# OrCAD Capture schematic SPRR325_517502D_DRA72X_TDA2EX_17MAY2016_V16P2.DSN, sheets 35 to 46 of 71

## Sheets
35 SH45 - SERDES CLOCK: size B; rev: A
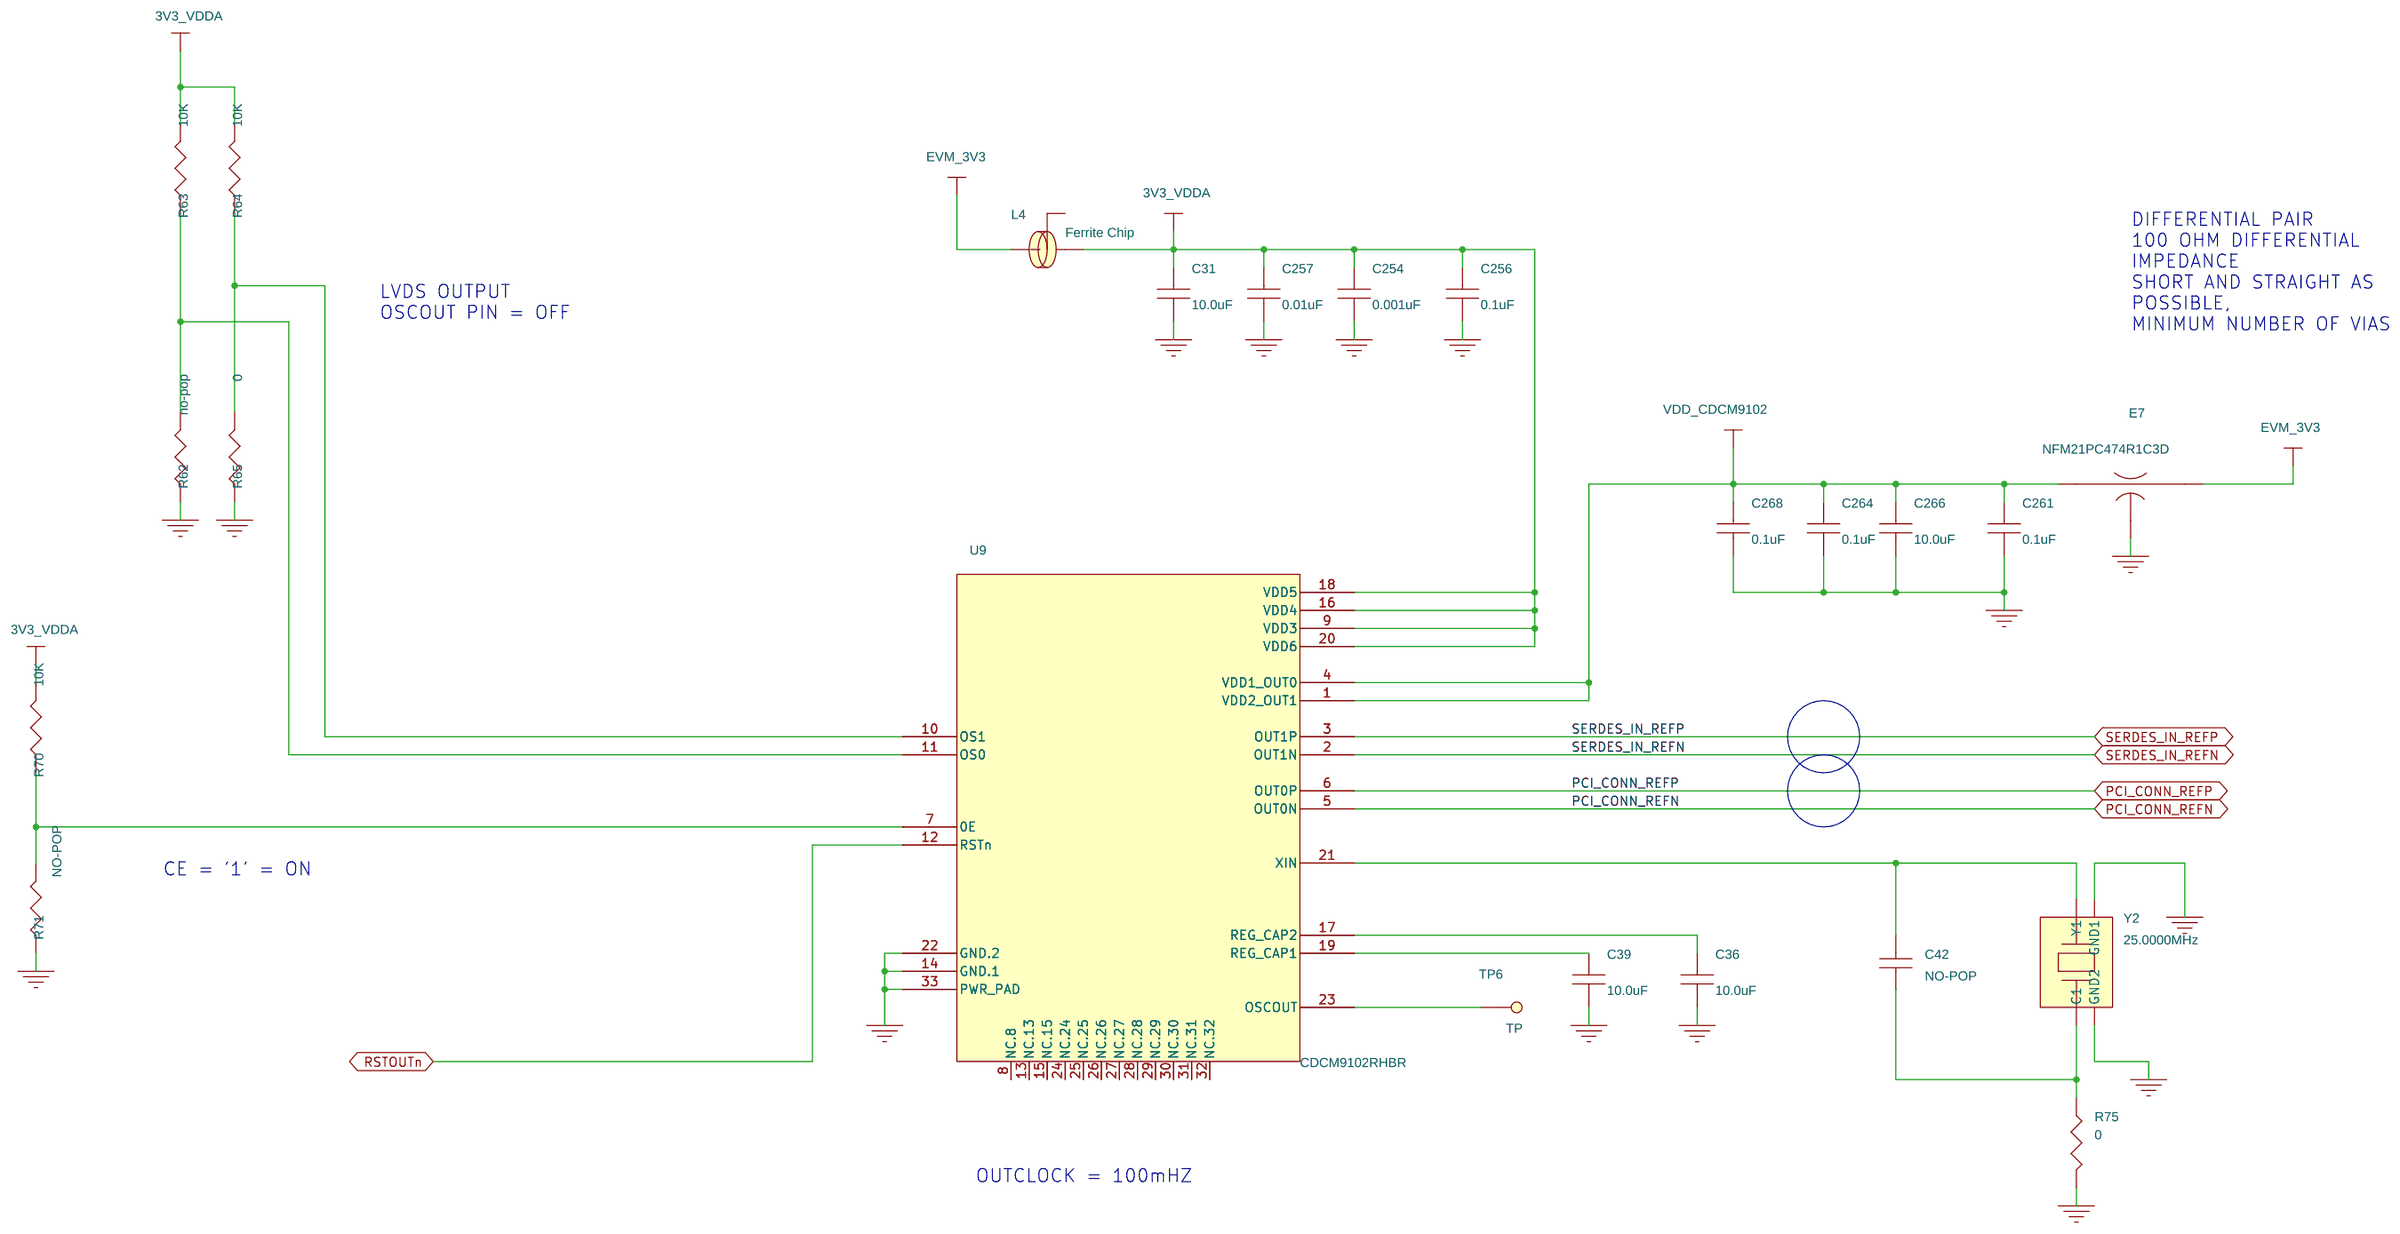
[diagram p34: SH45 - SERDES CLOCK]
36 SH46 - PCIe CONNECTORS: size B; rev: B
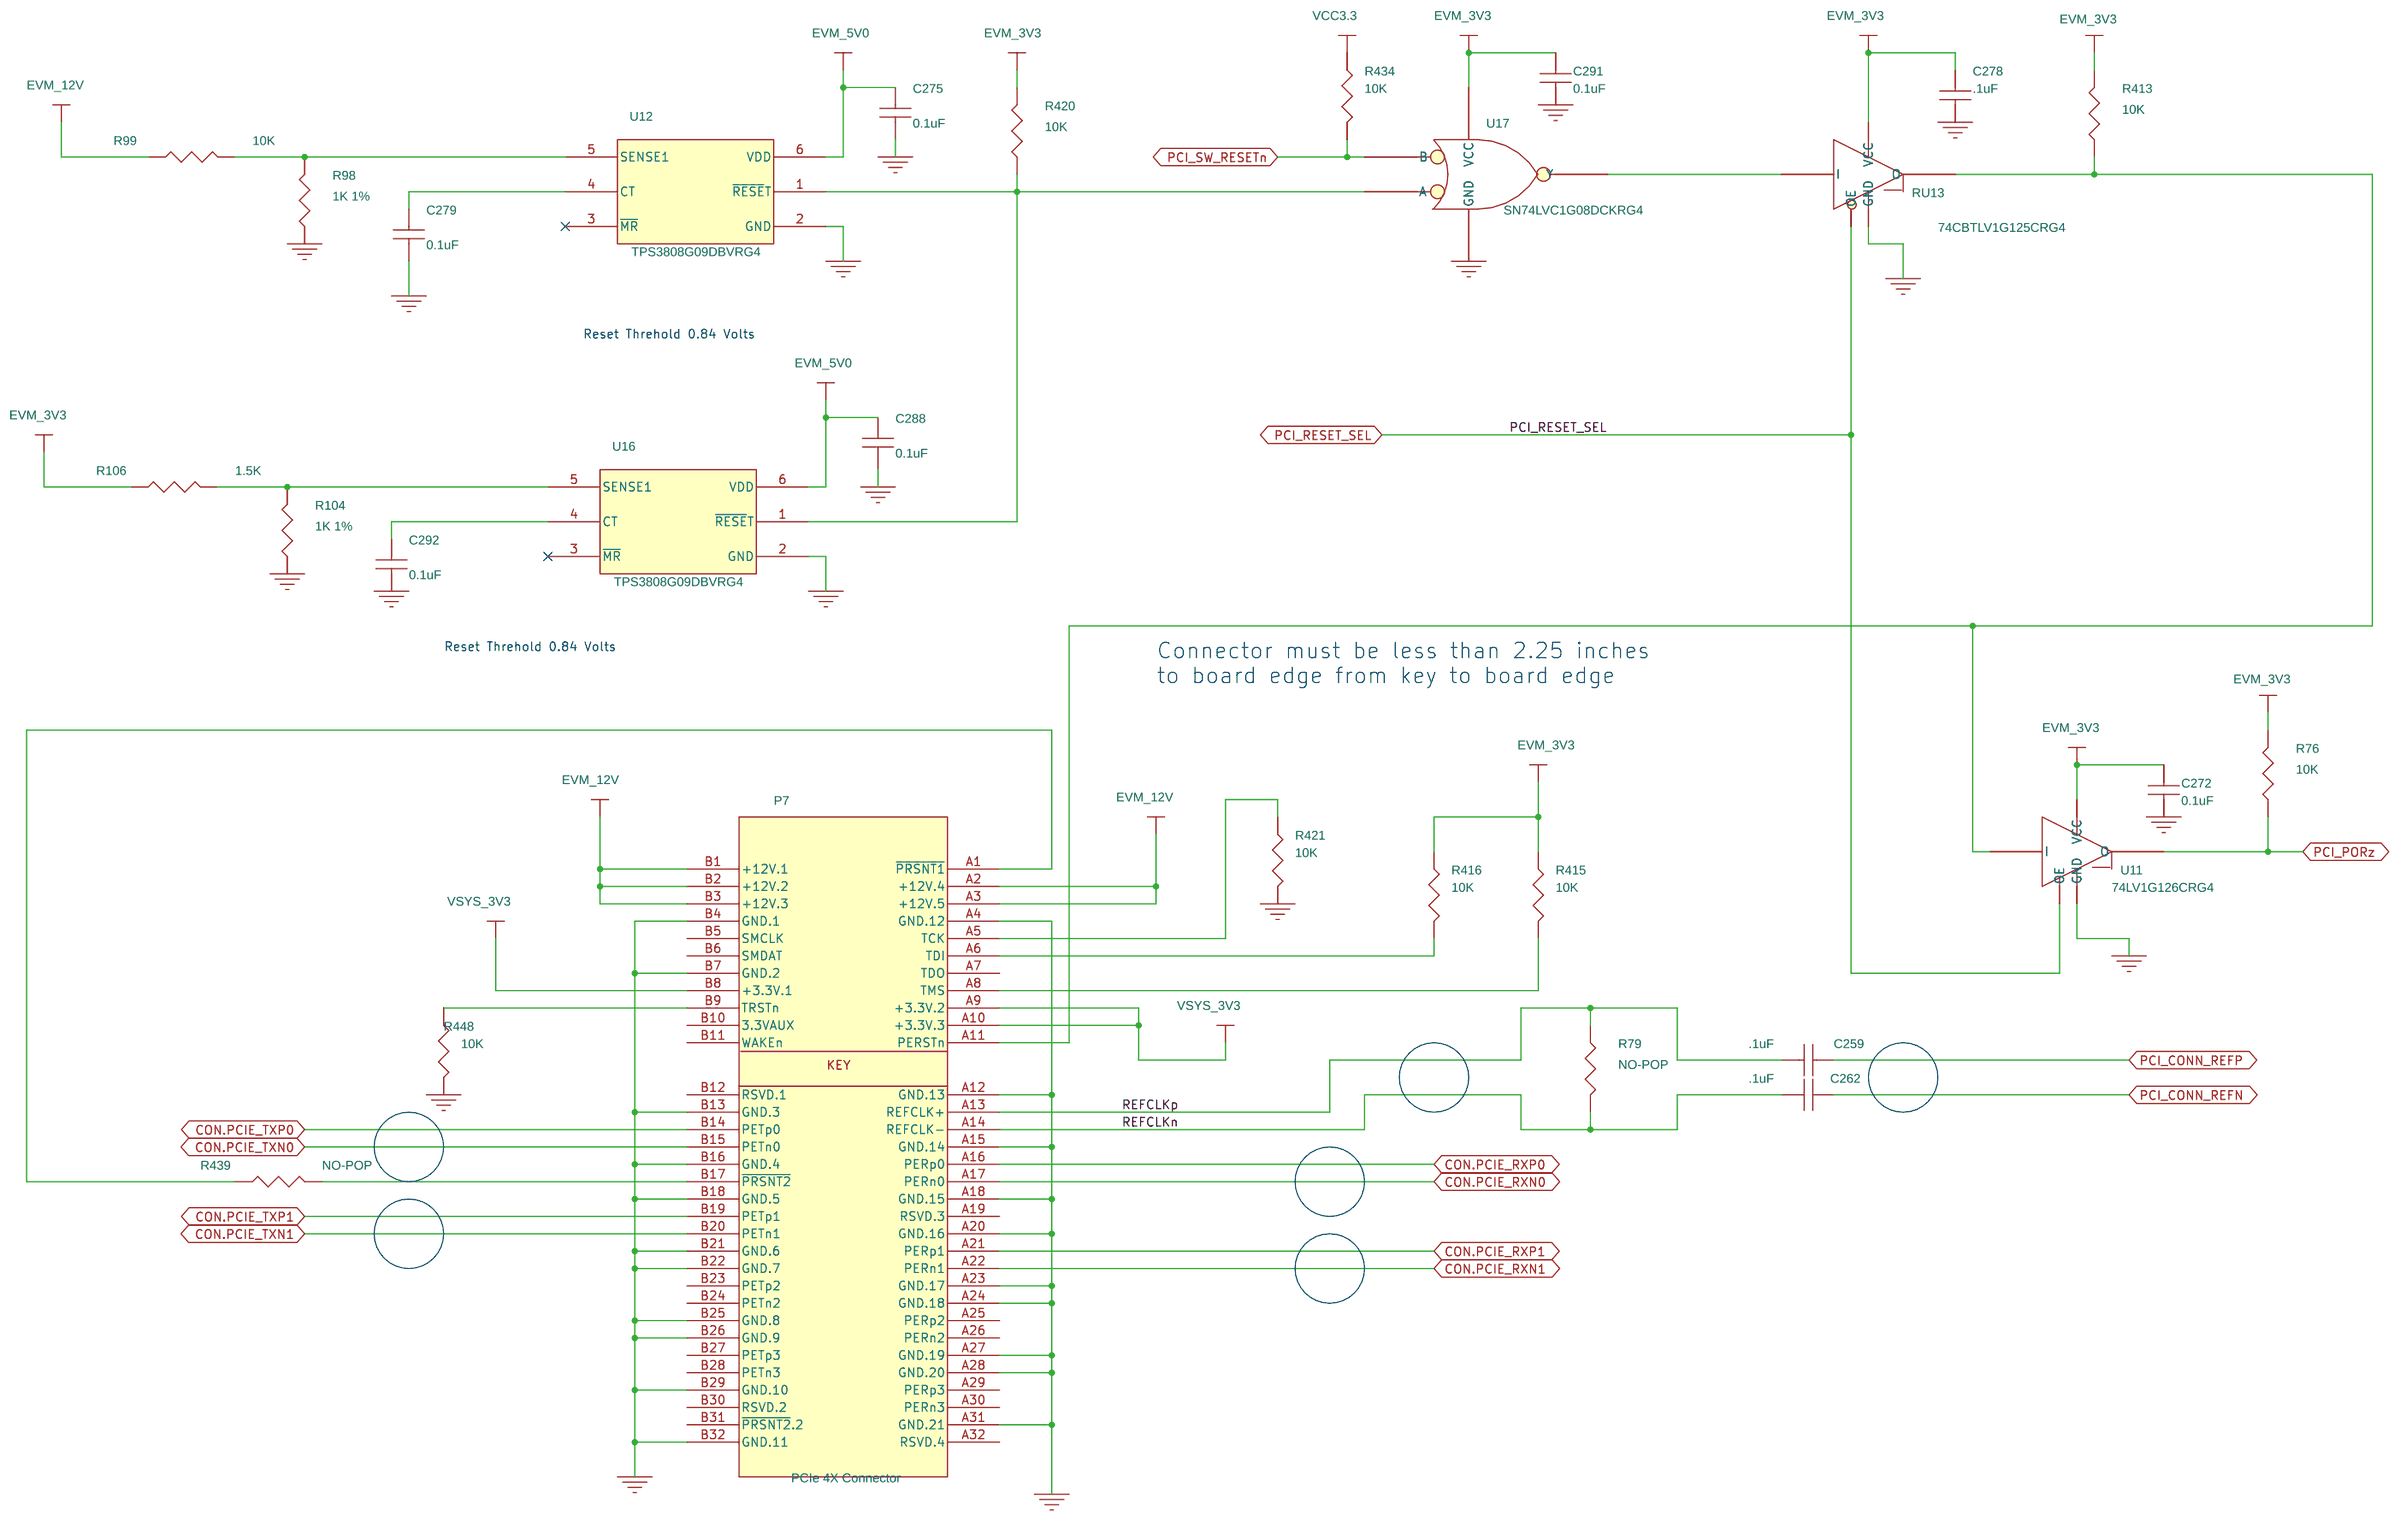
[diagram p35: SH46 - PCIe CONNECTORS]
37 SH47 - LCD CONNECTOR: size B; rev: A
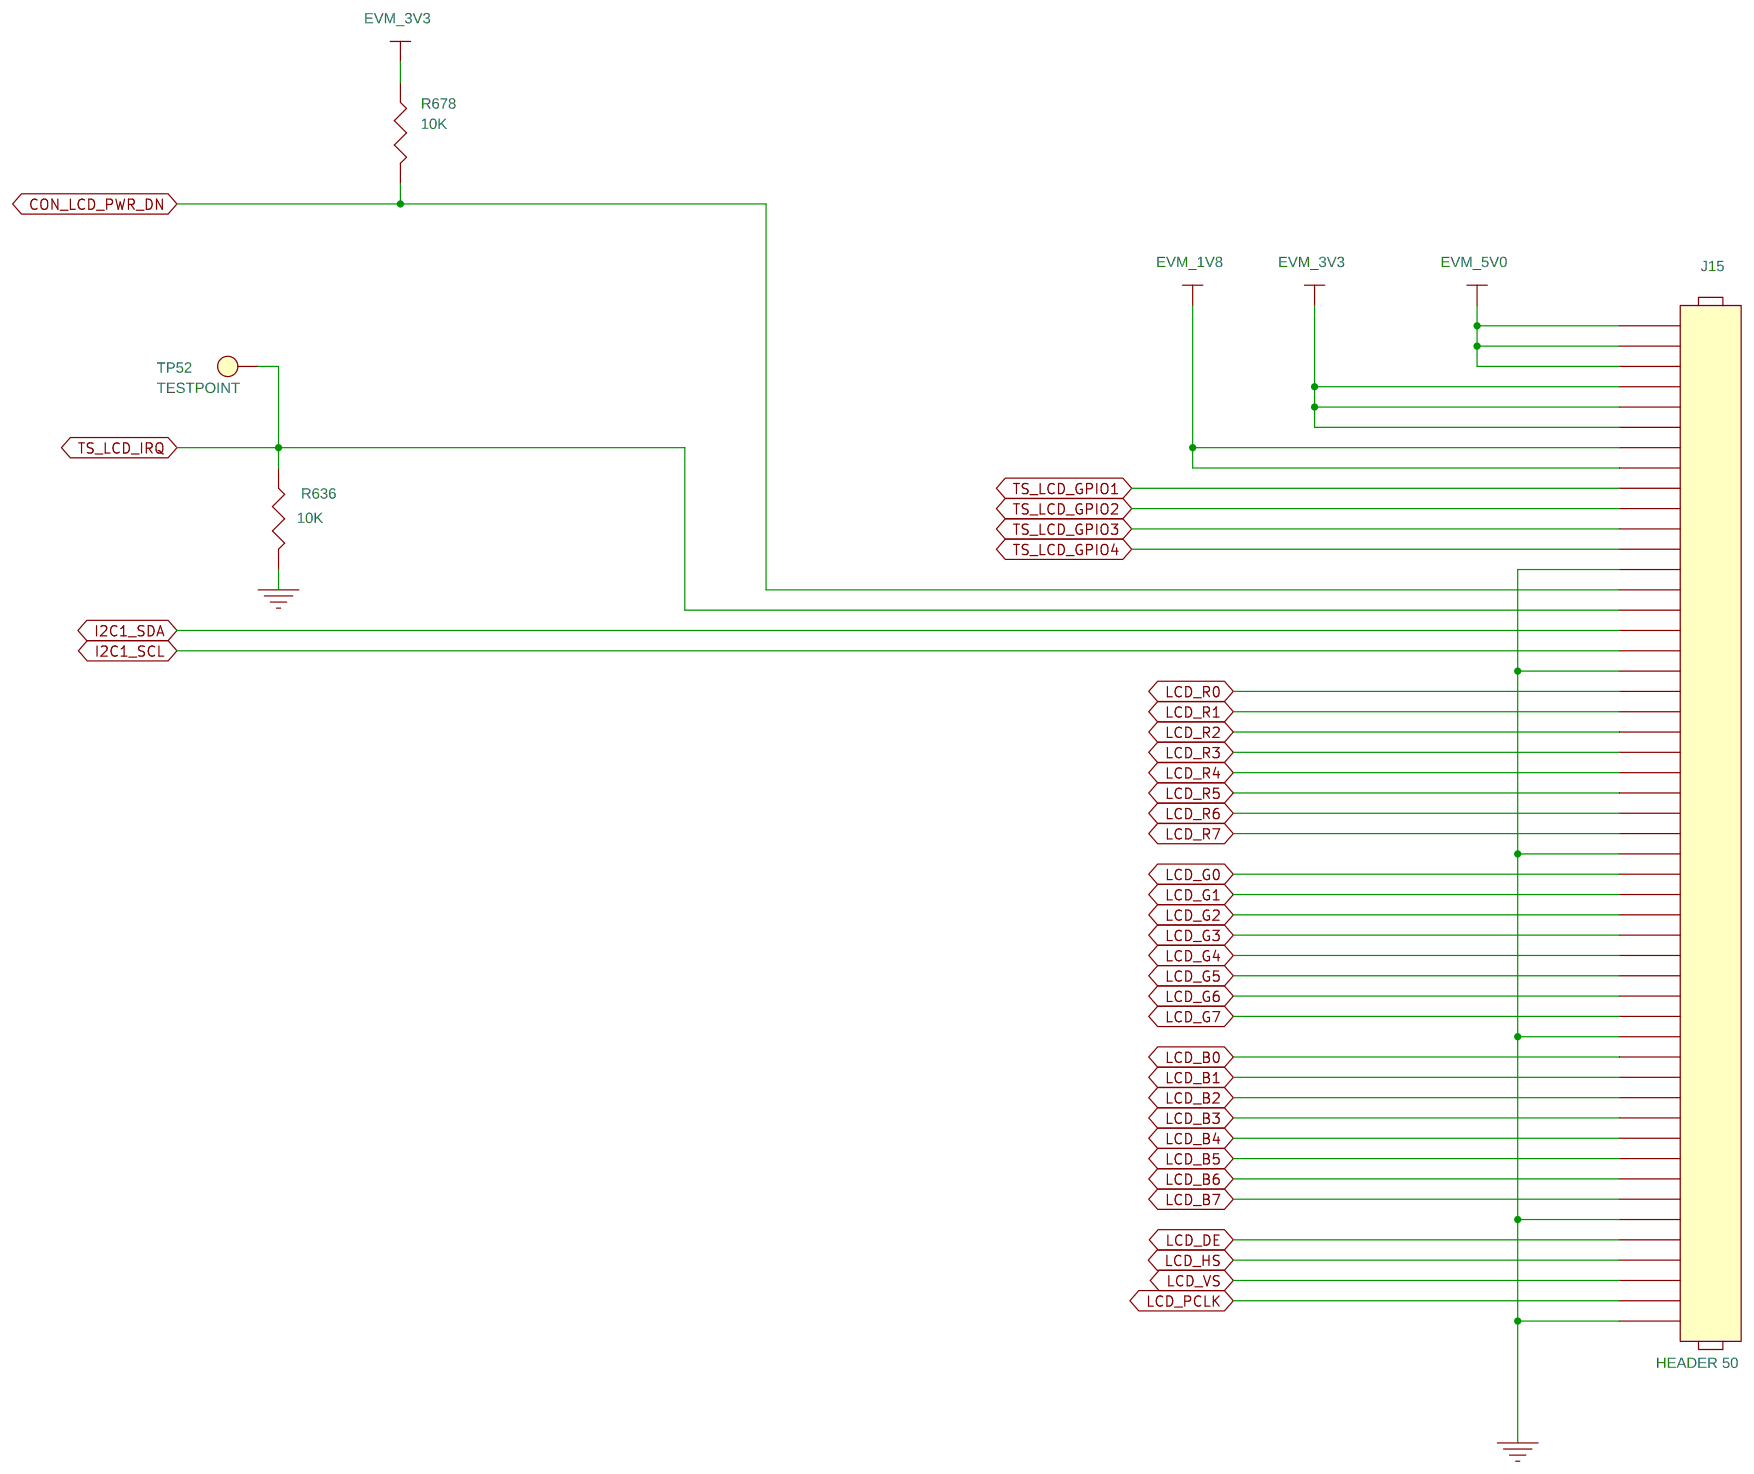
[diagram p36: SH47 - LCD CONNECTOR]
38 SH48 - HDMI OUTPUT CONNECTOR: size B; rev: C
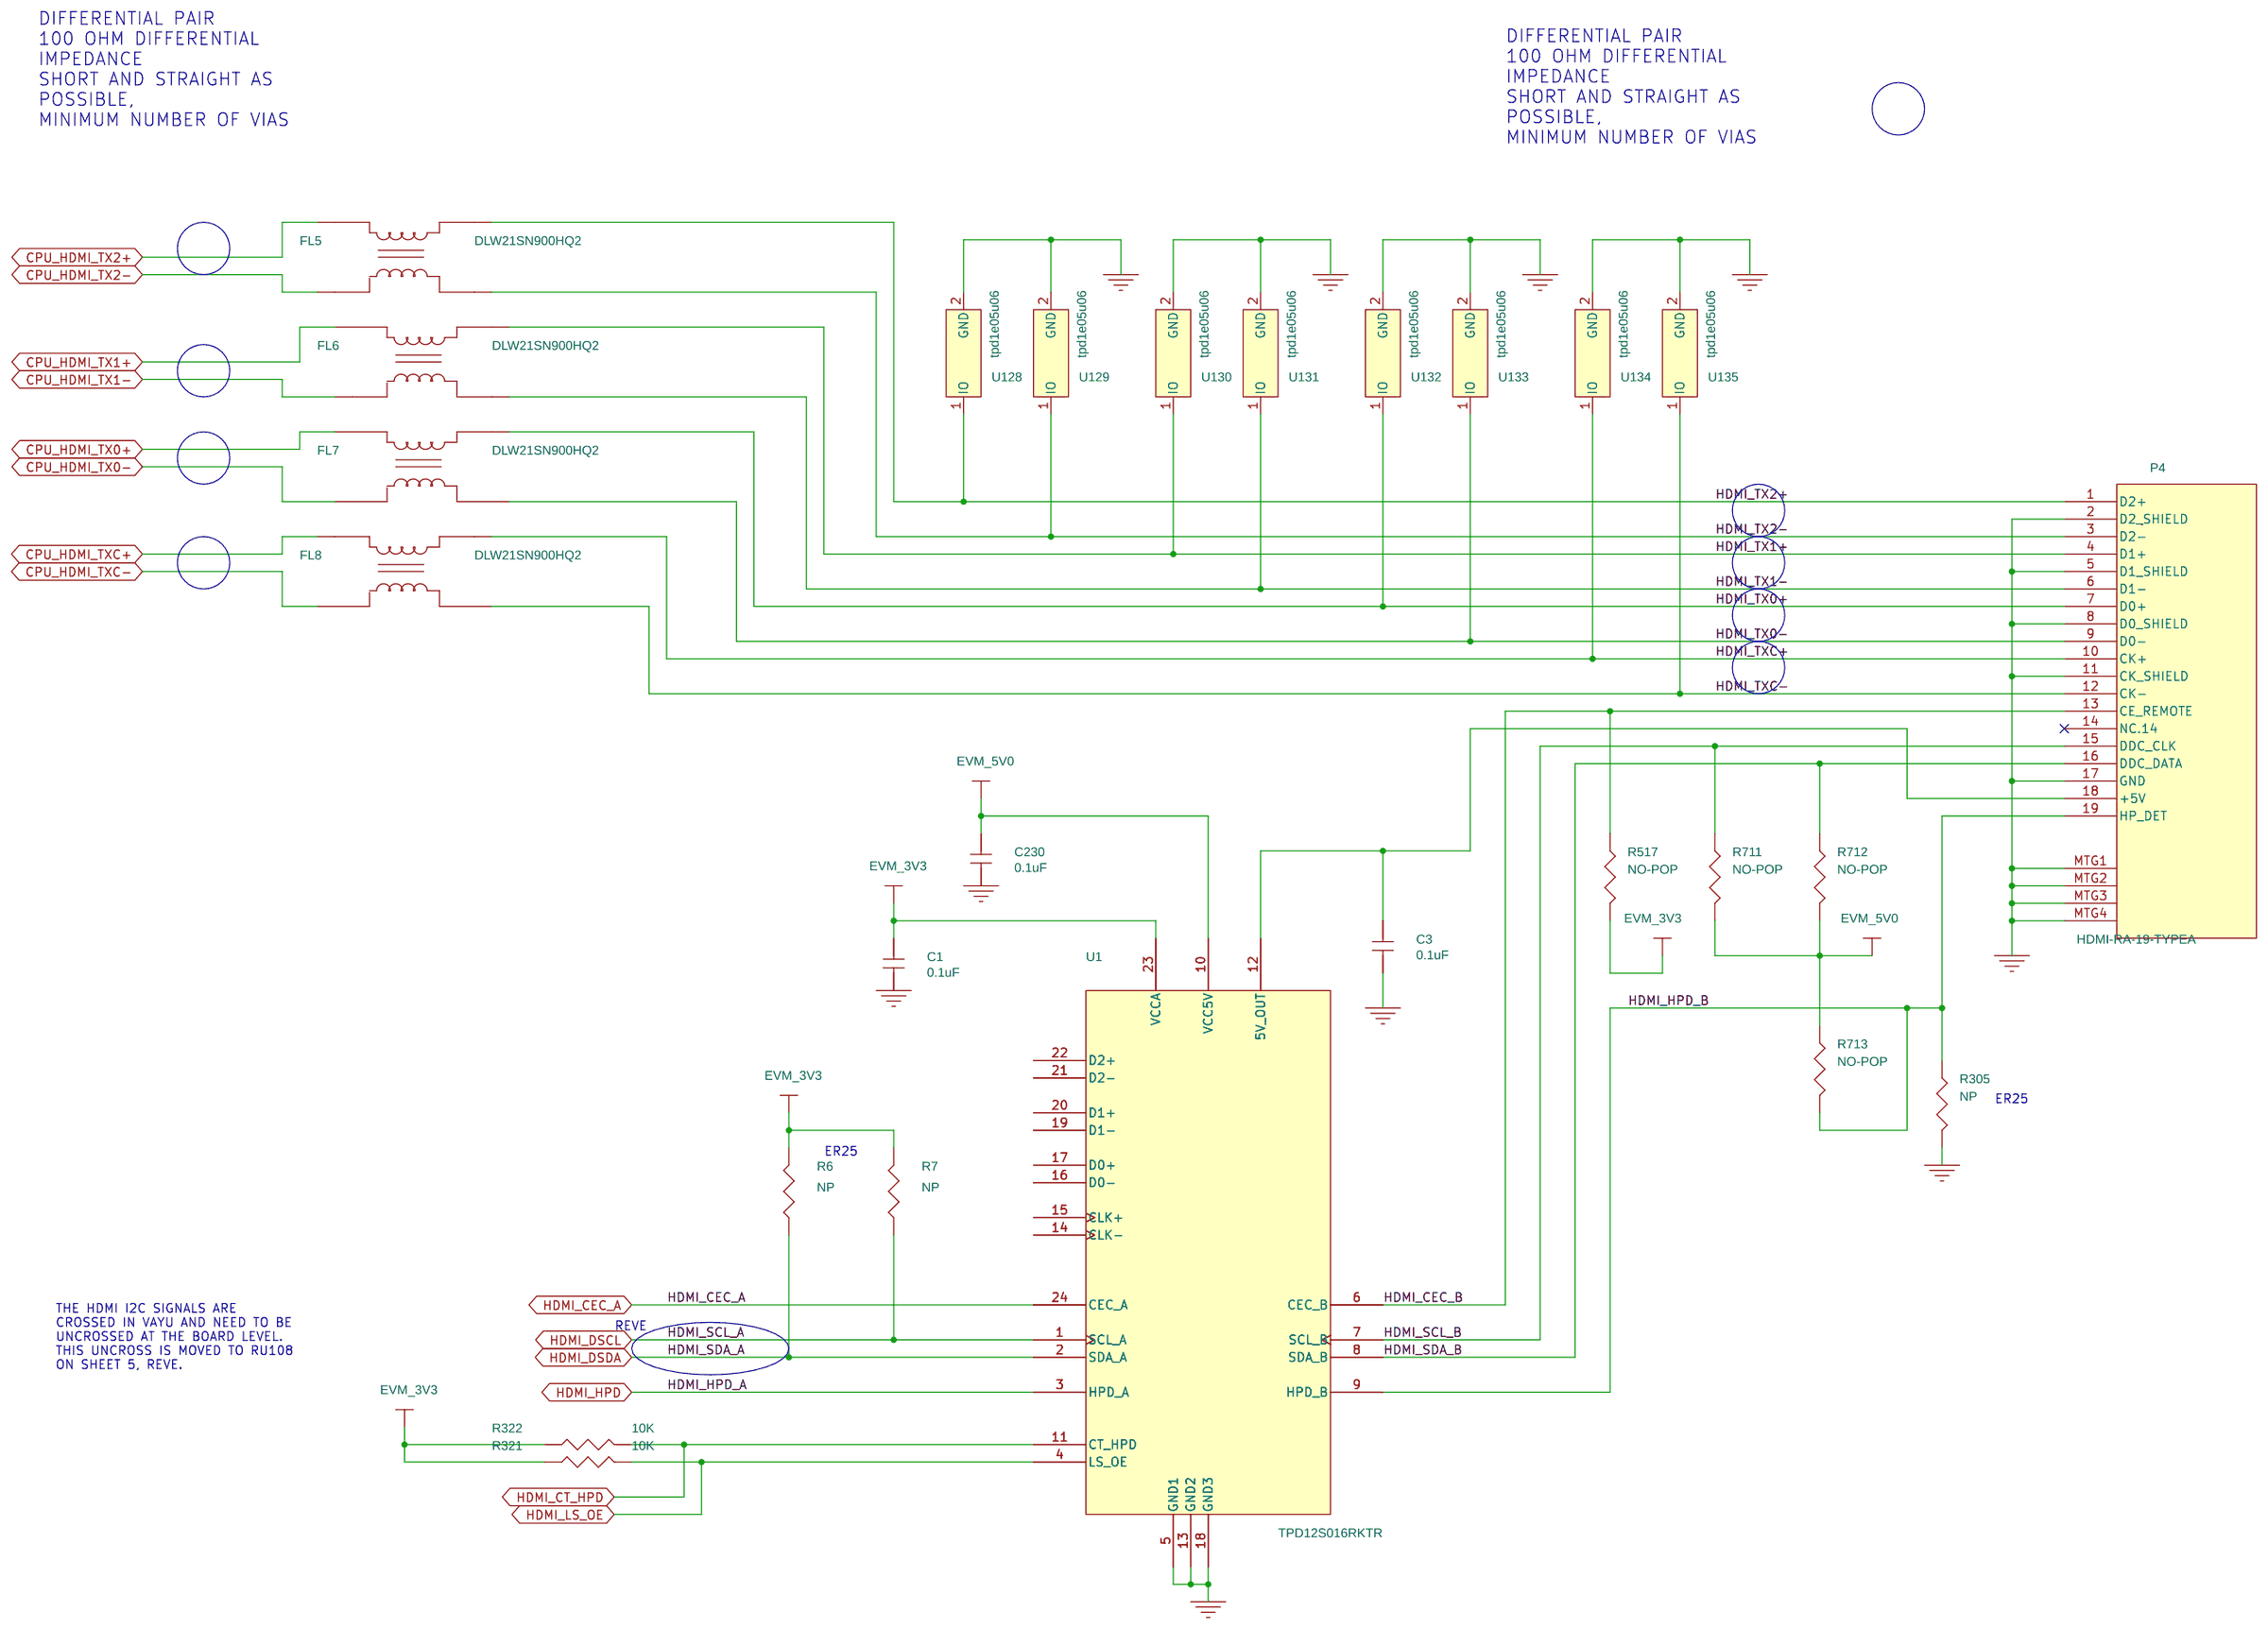
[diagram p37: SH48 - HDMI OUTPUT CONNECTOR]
39 SH49 - FPD LINK: size B; rev: A
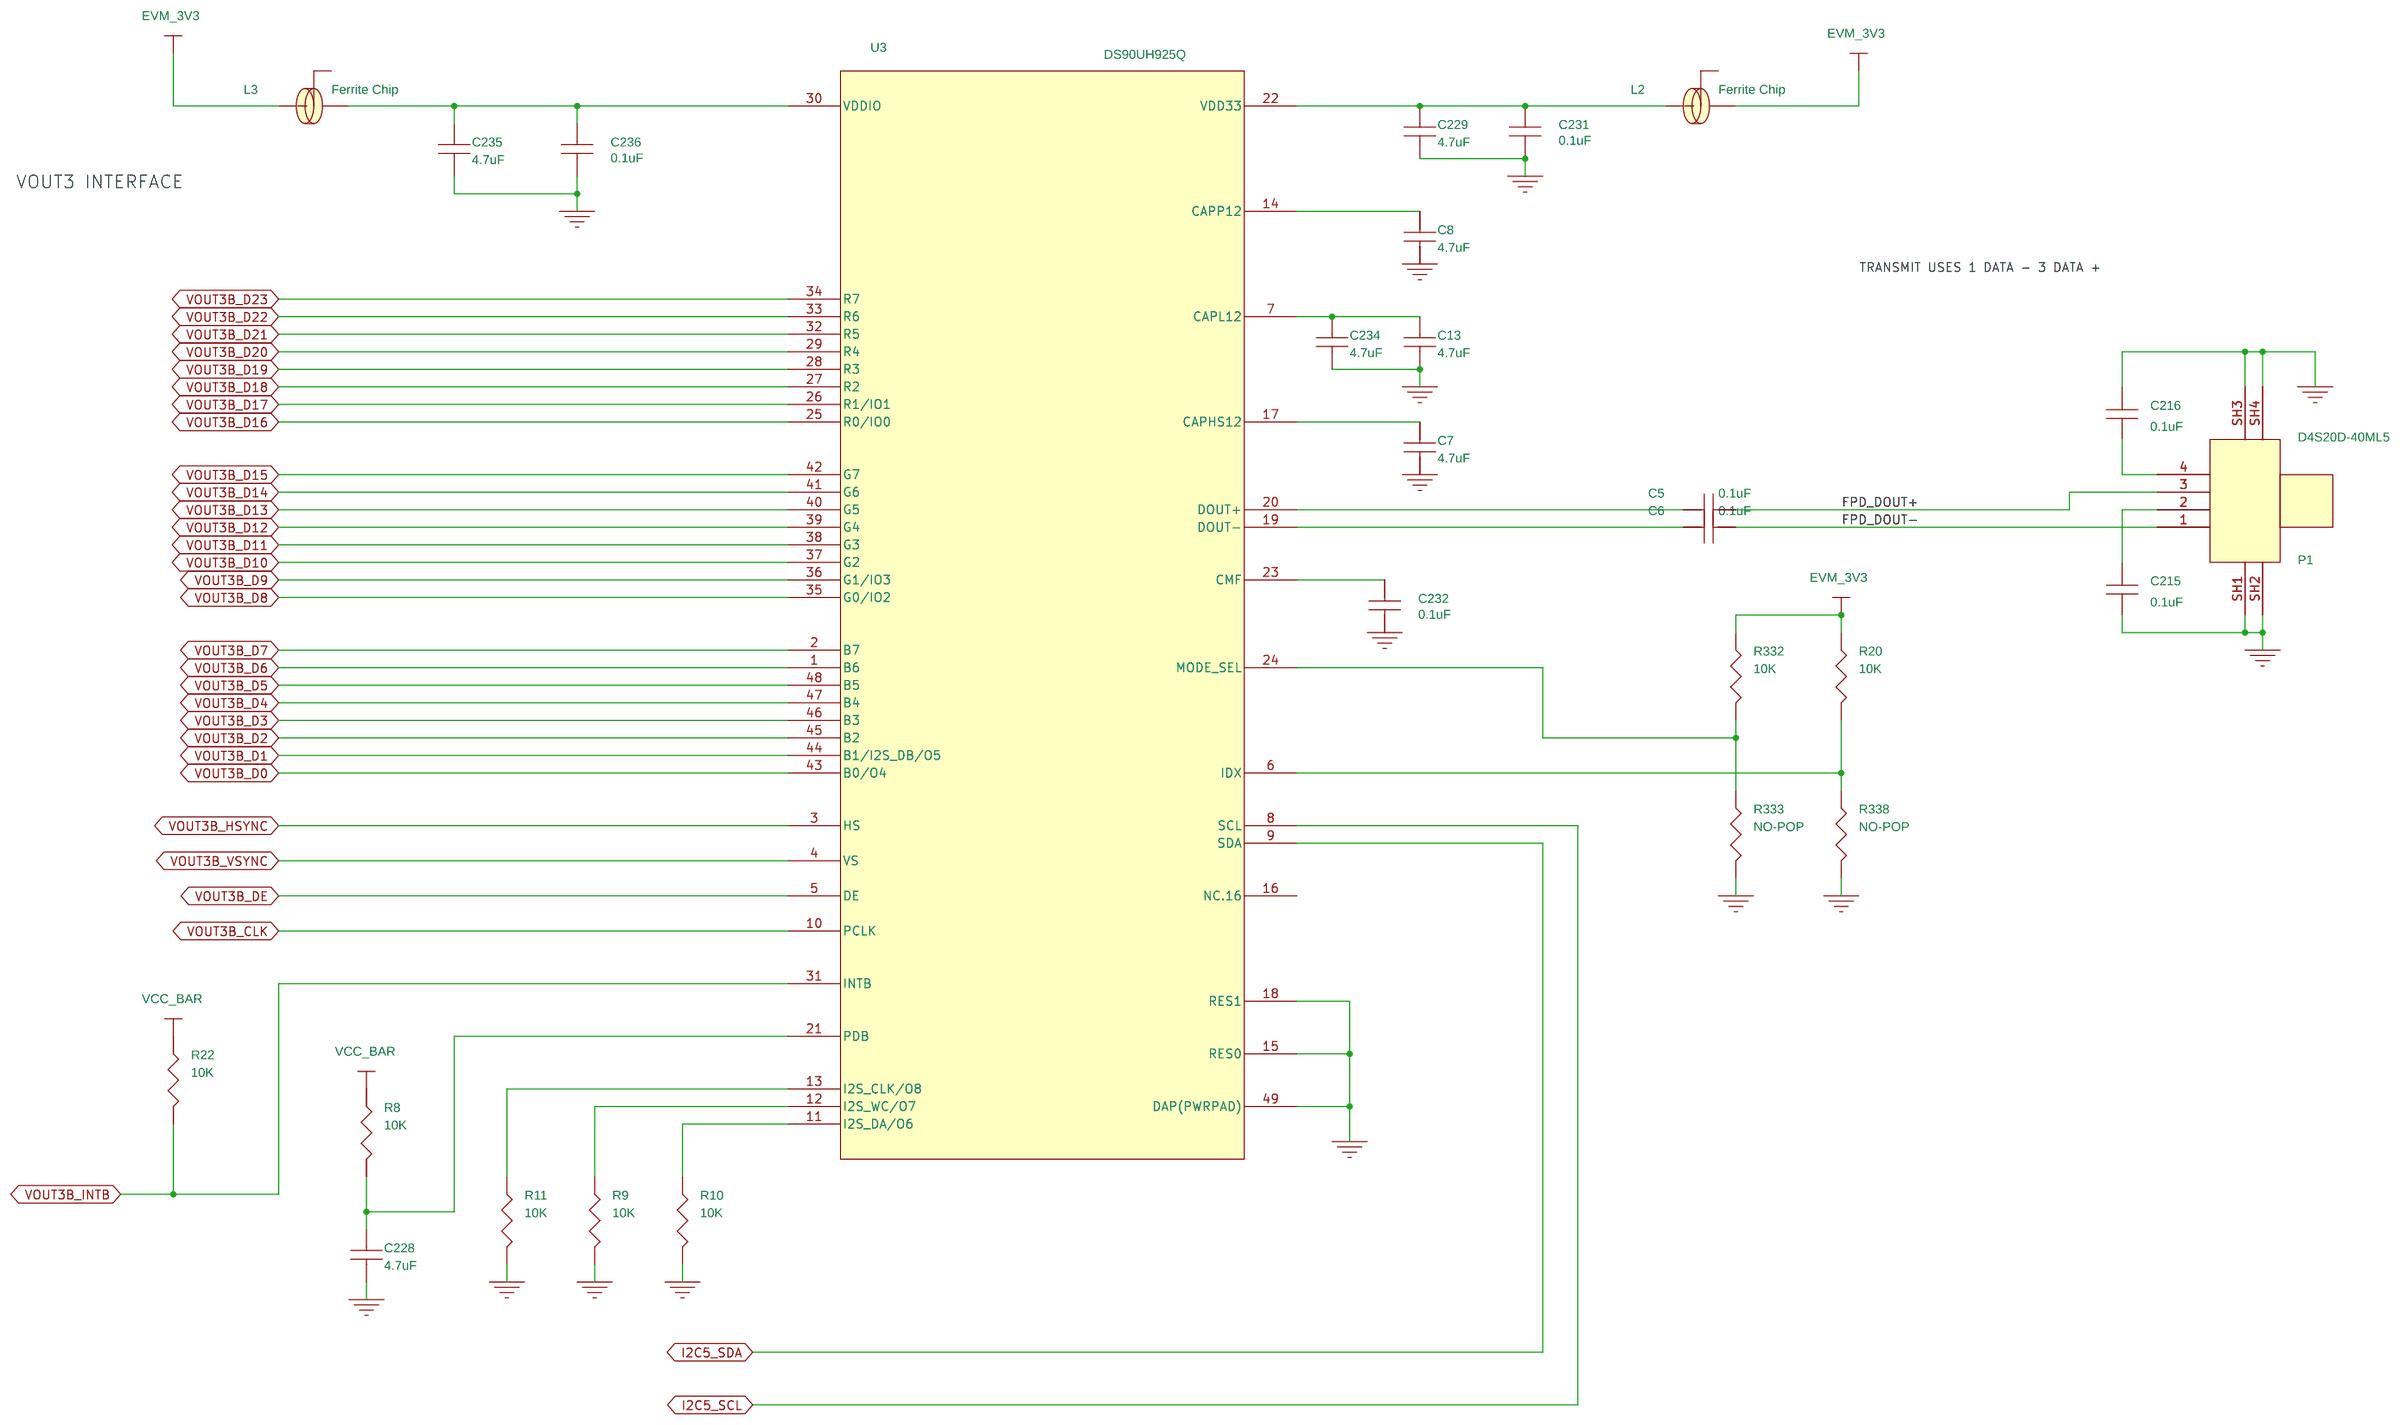
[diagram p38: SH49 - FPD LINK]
40 SH50 - CAMERA IF: size B; rev: B
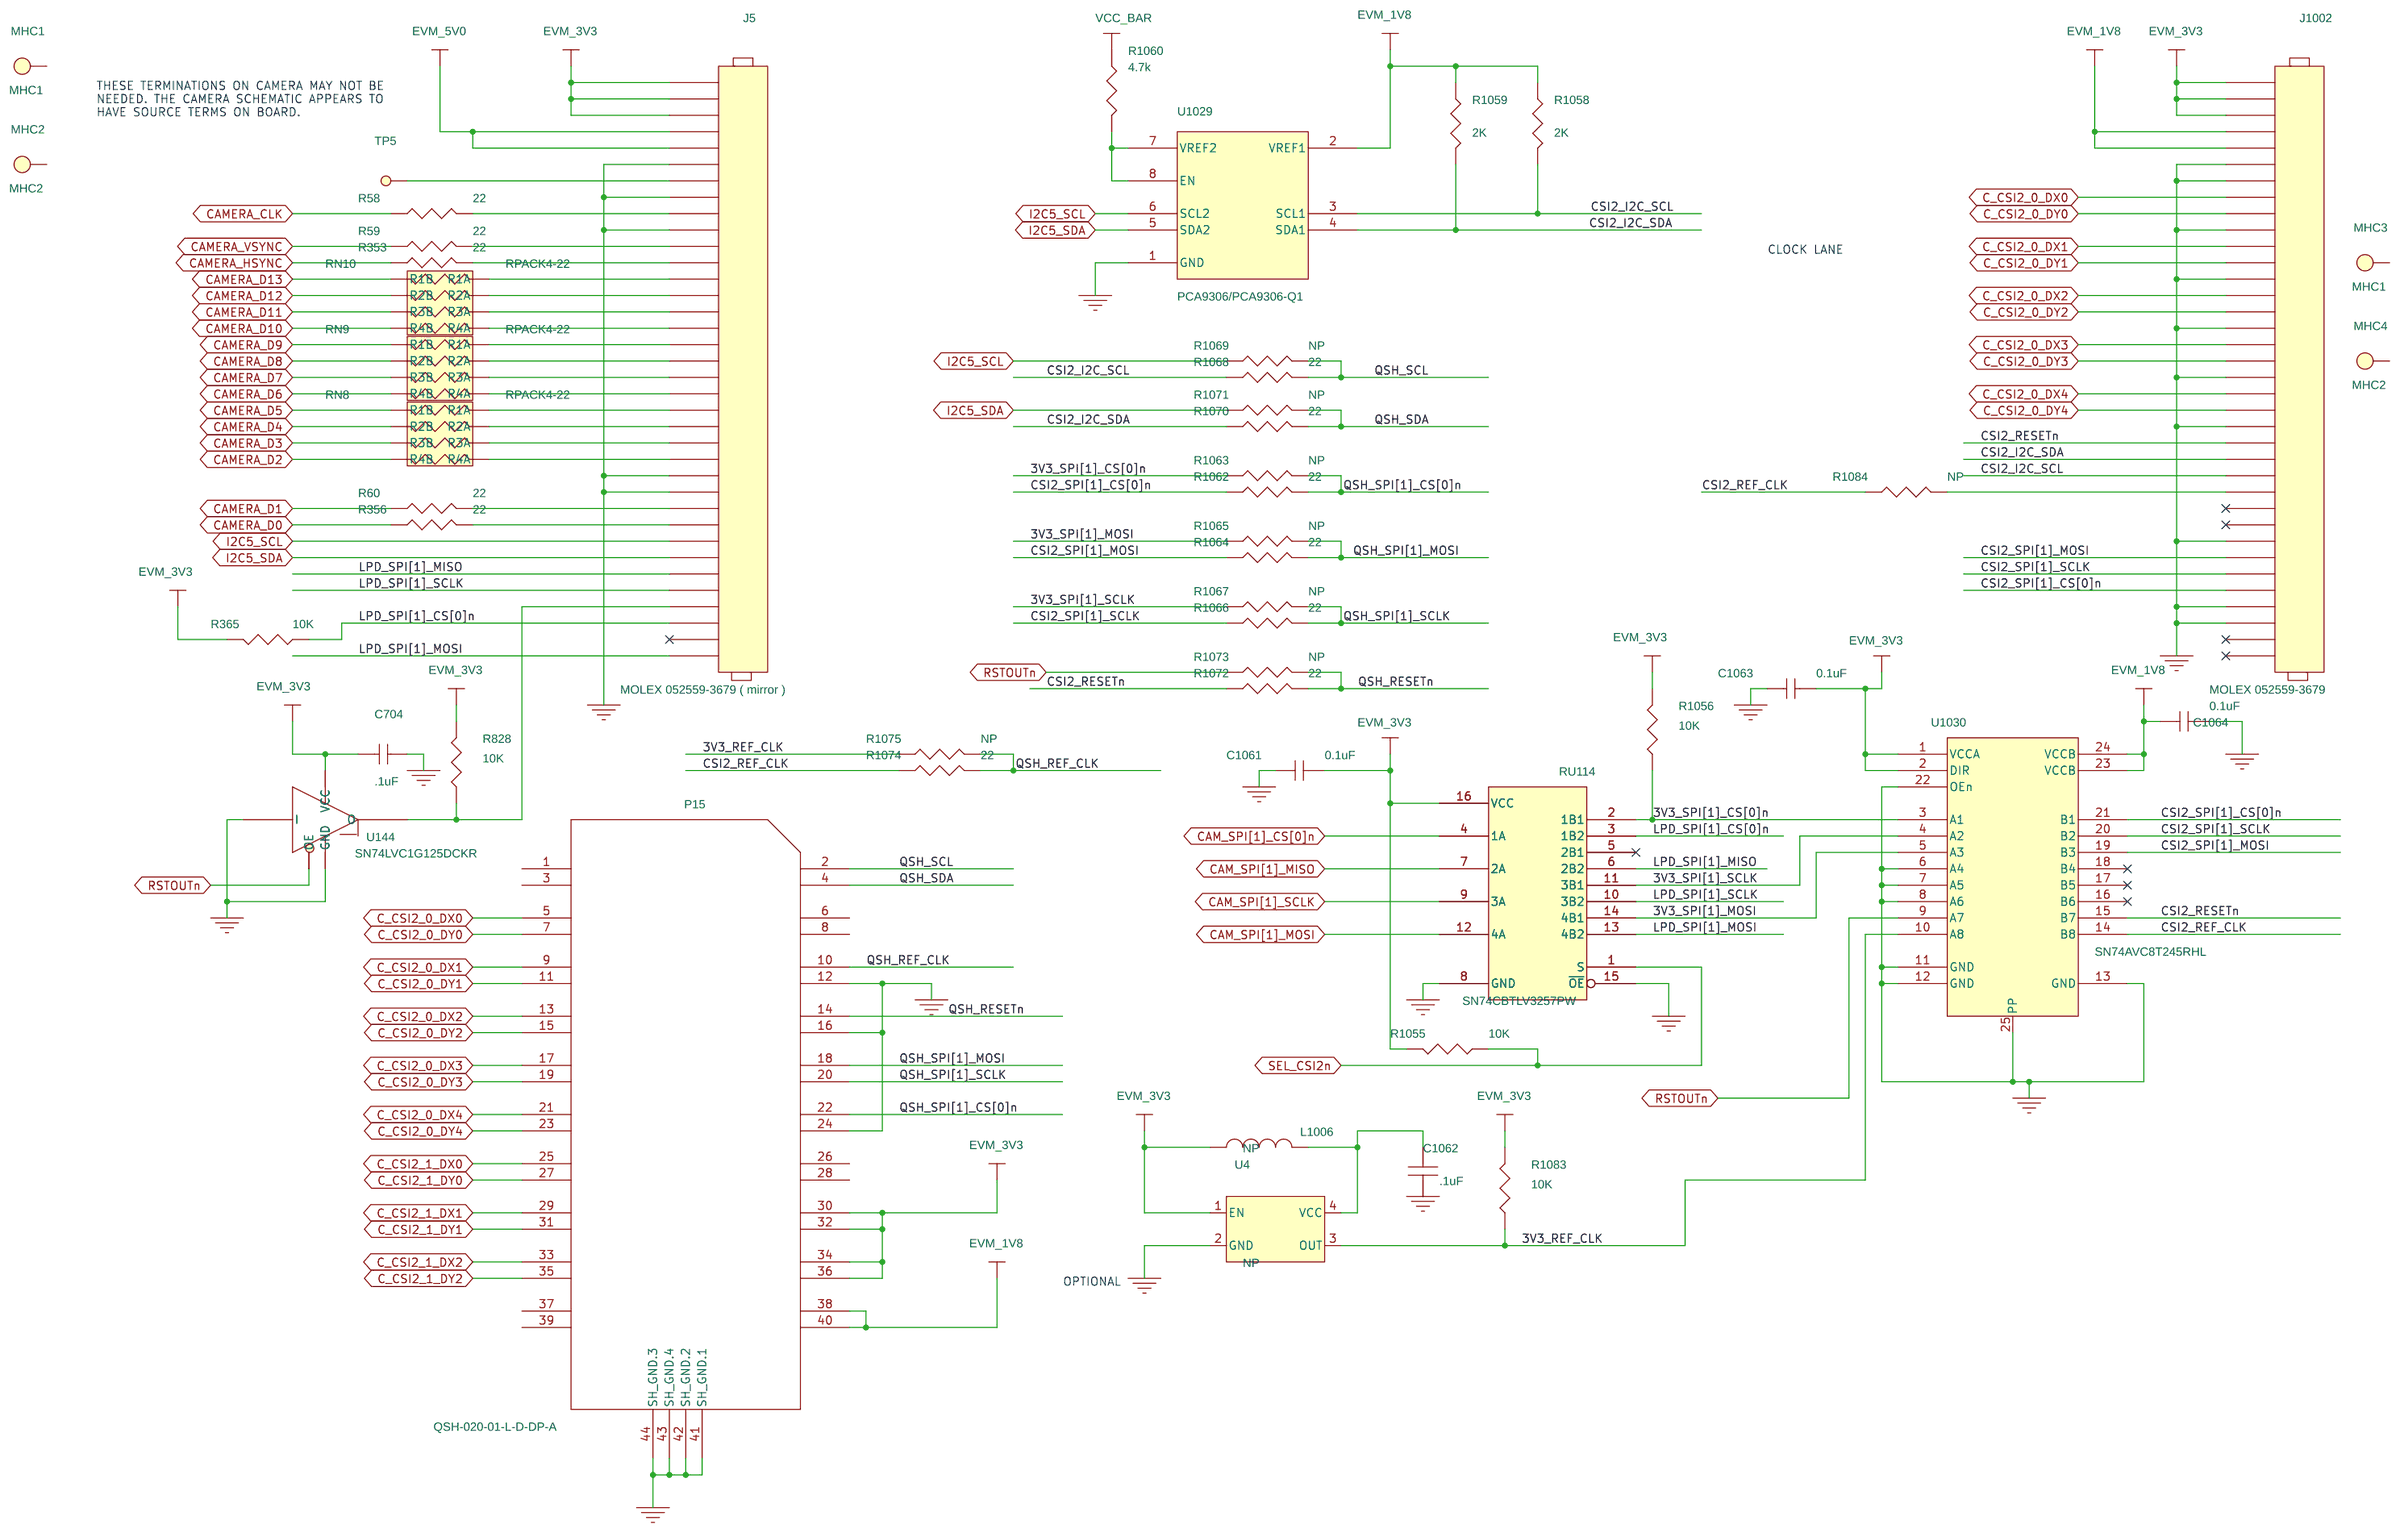
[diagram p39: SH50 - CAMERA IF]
41 SH51 - CAN CONNECTORS: size B; rev: A
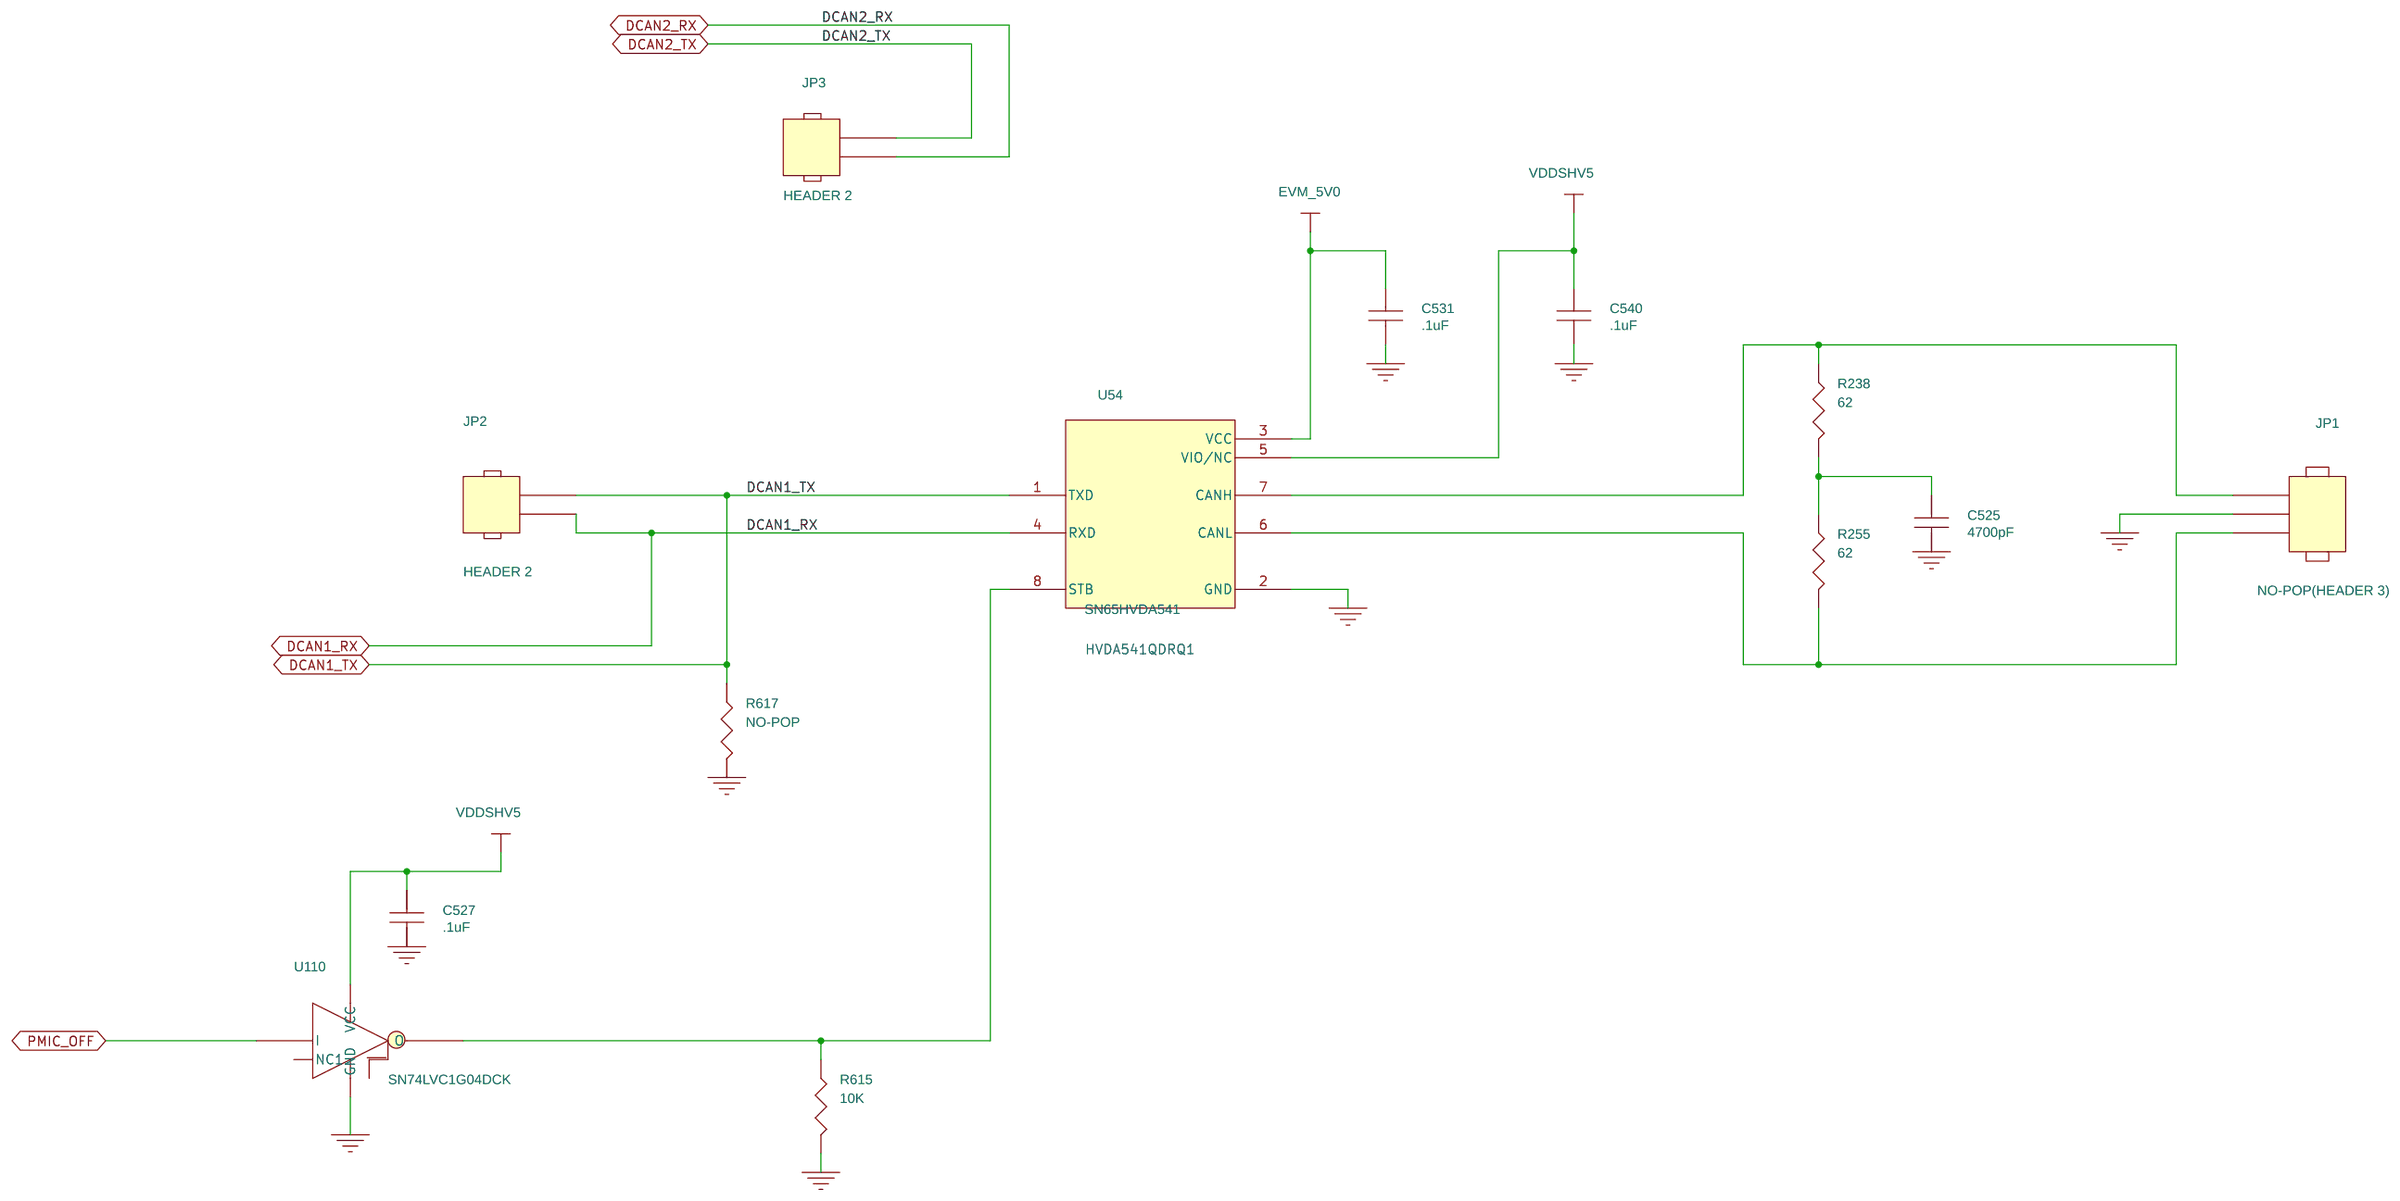
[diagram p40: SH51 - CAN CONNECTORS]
42 SH53 - I2C EXPANDER: size B; rev: A
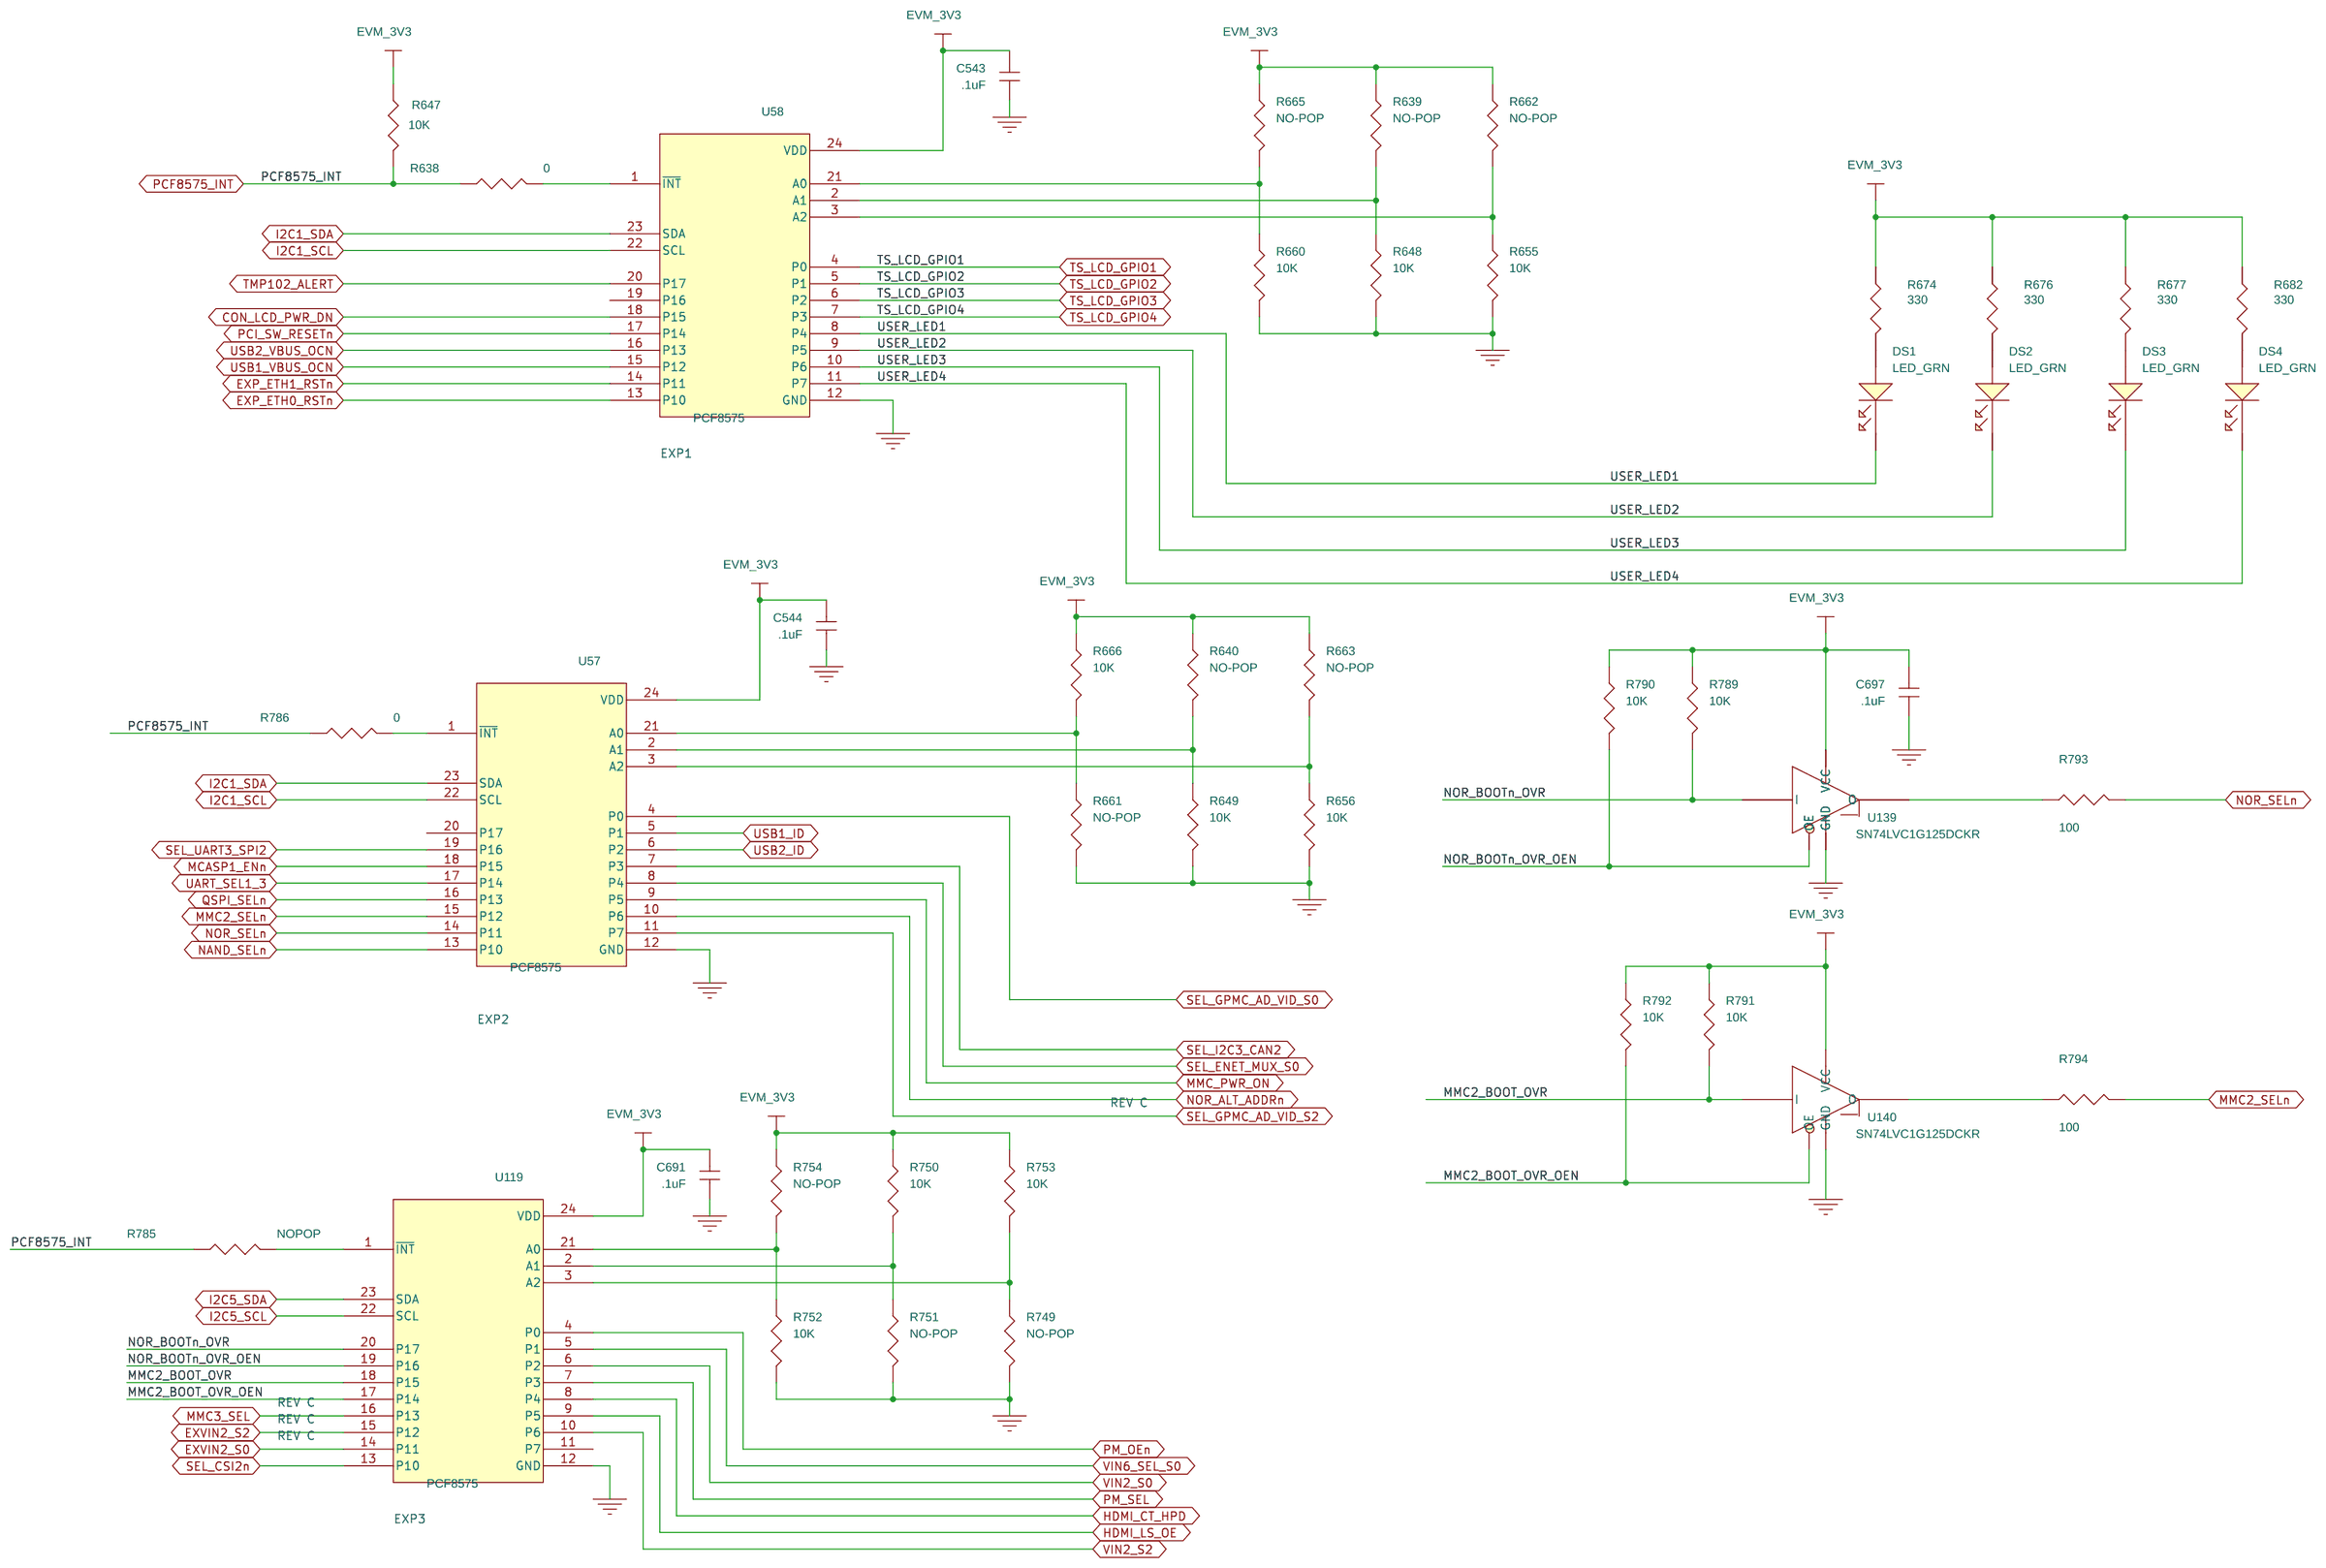
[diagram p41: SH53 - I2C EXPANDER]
43 SH54 - BOOTSWITCHES: size B; rev: A
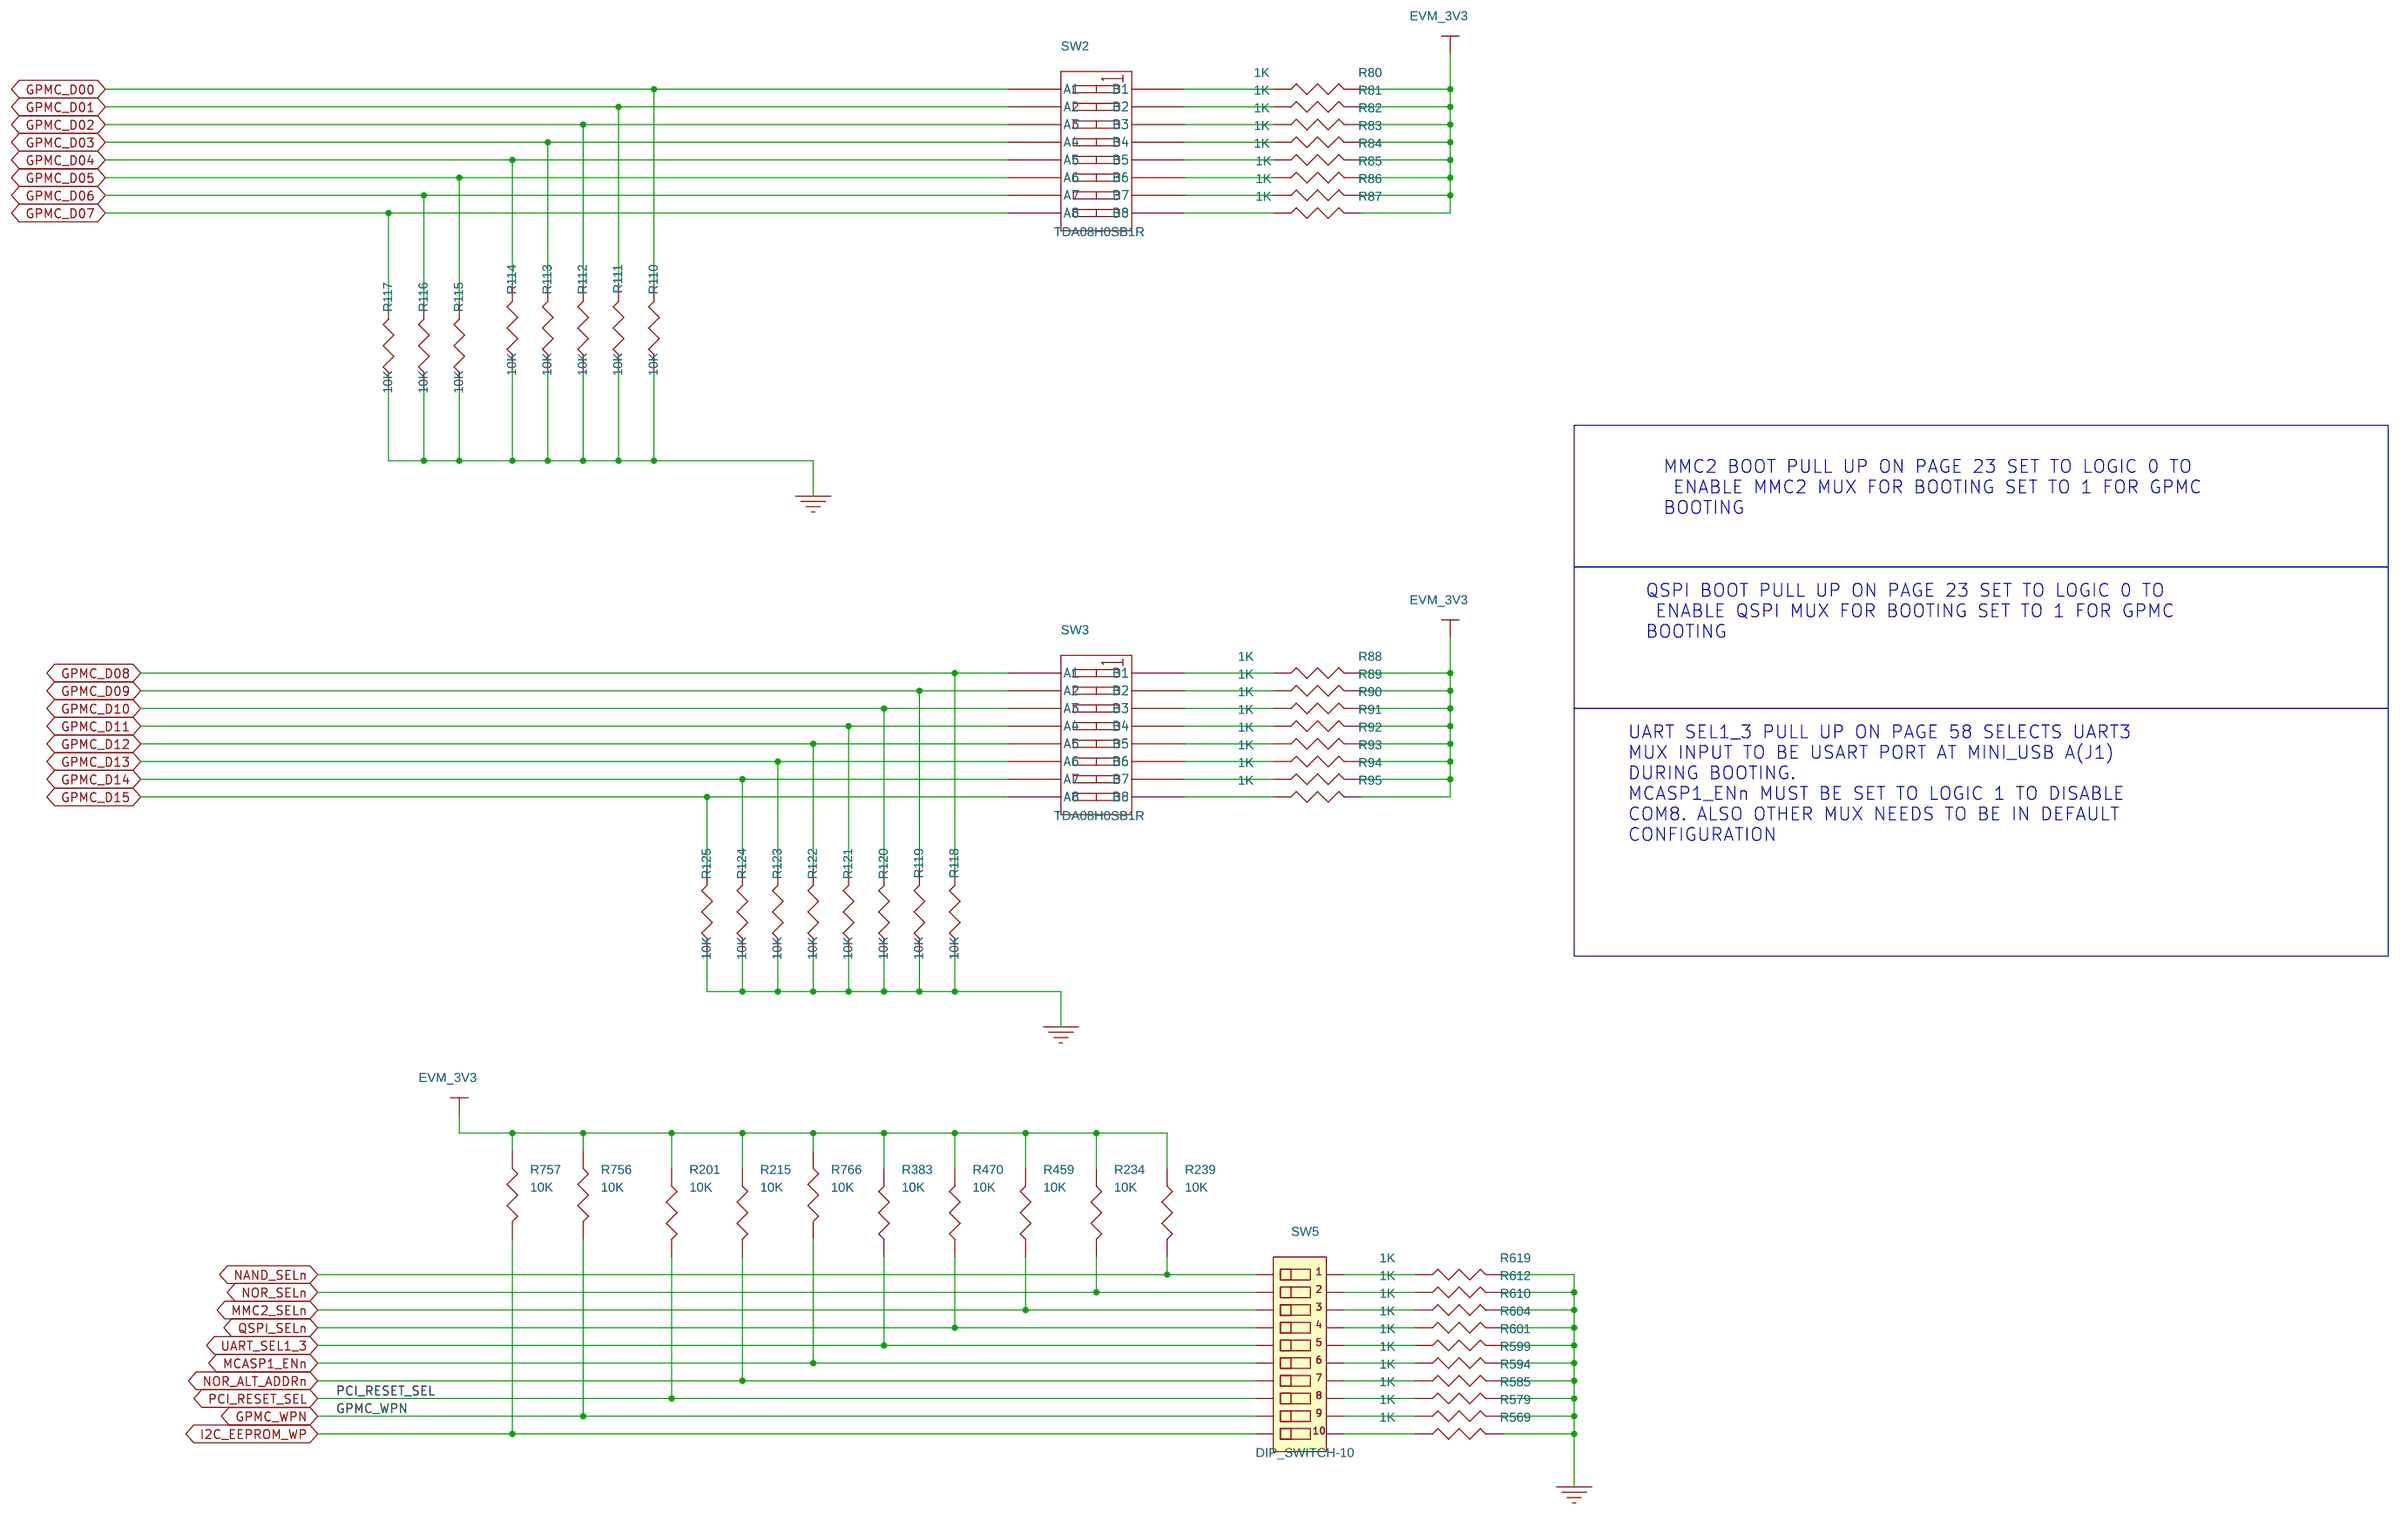
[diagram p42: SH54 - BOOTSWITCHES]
44 SH55 - COM8 LEVEL TRANSLATOR: size B; rev: A
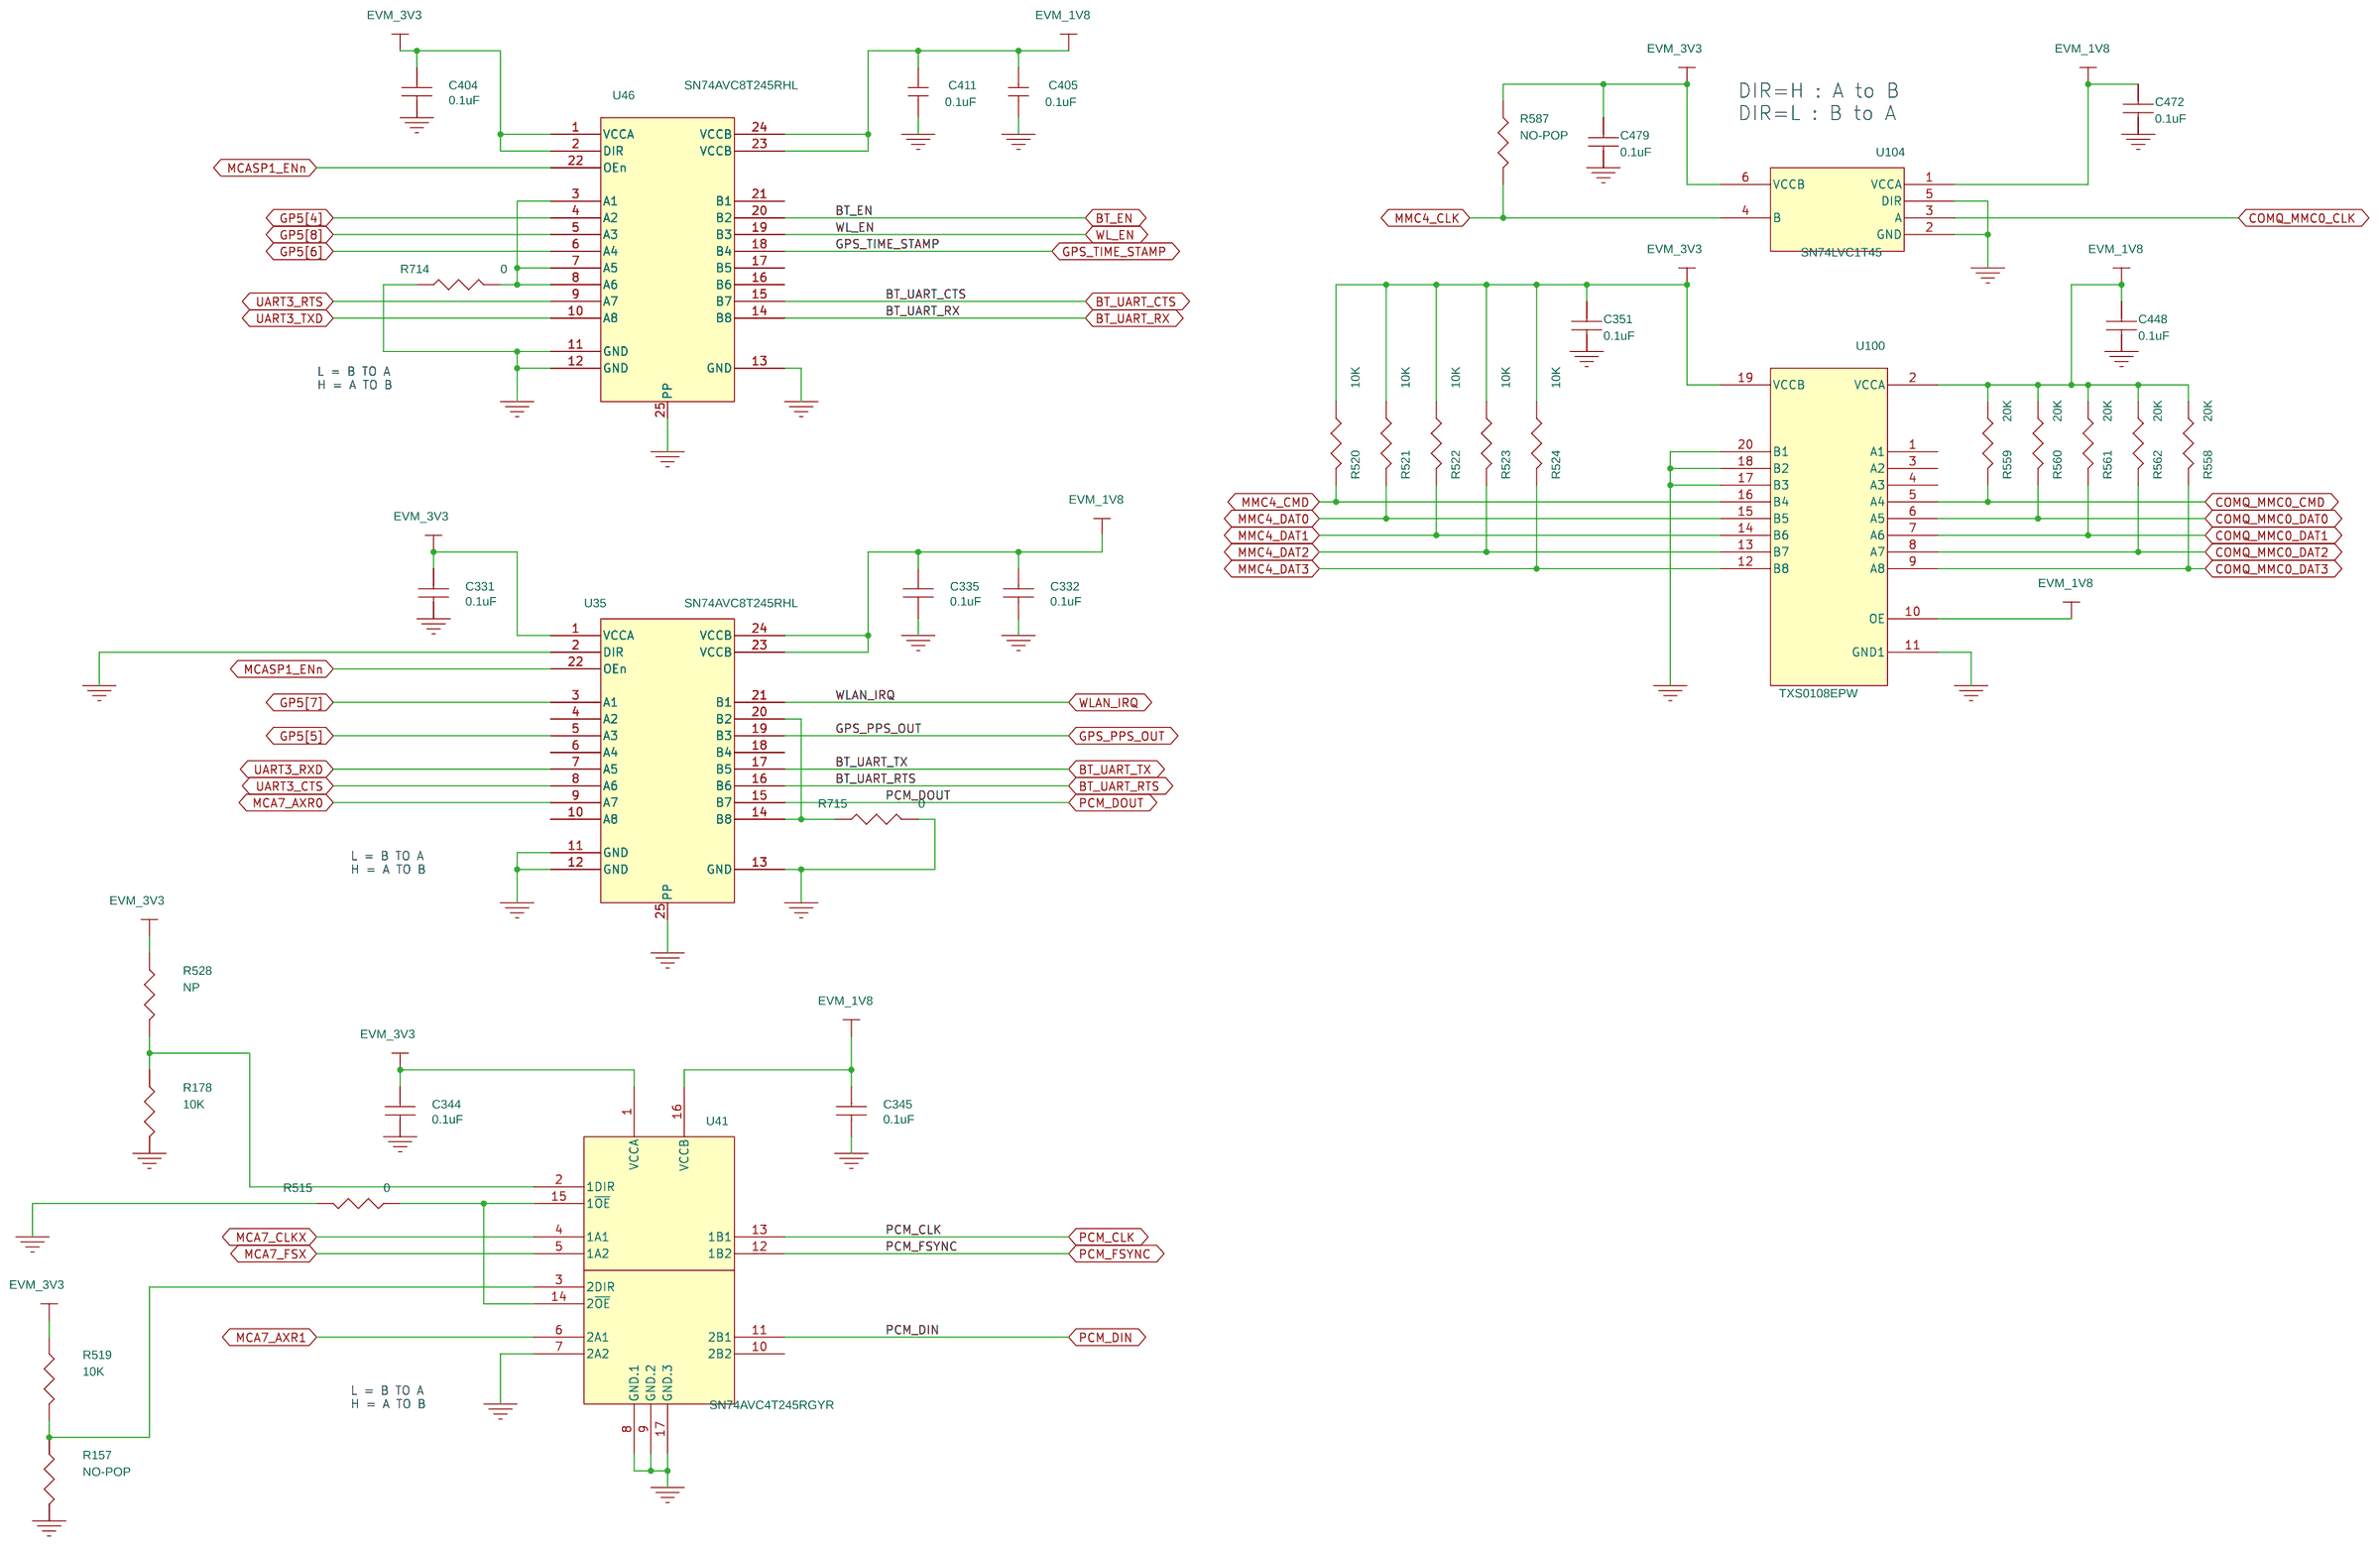
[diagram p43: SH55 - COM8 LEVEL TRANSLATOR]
45 SH56 - COM8 CONNECTOR: size B; rev: A
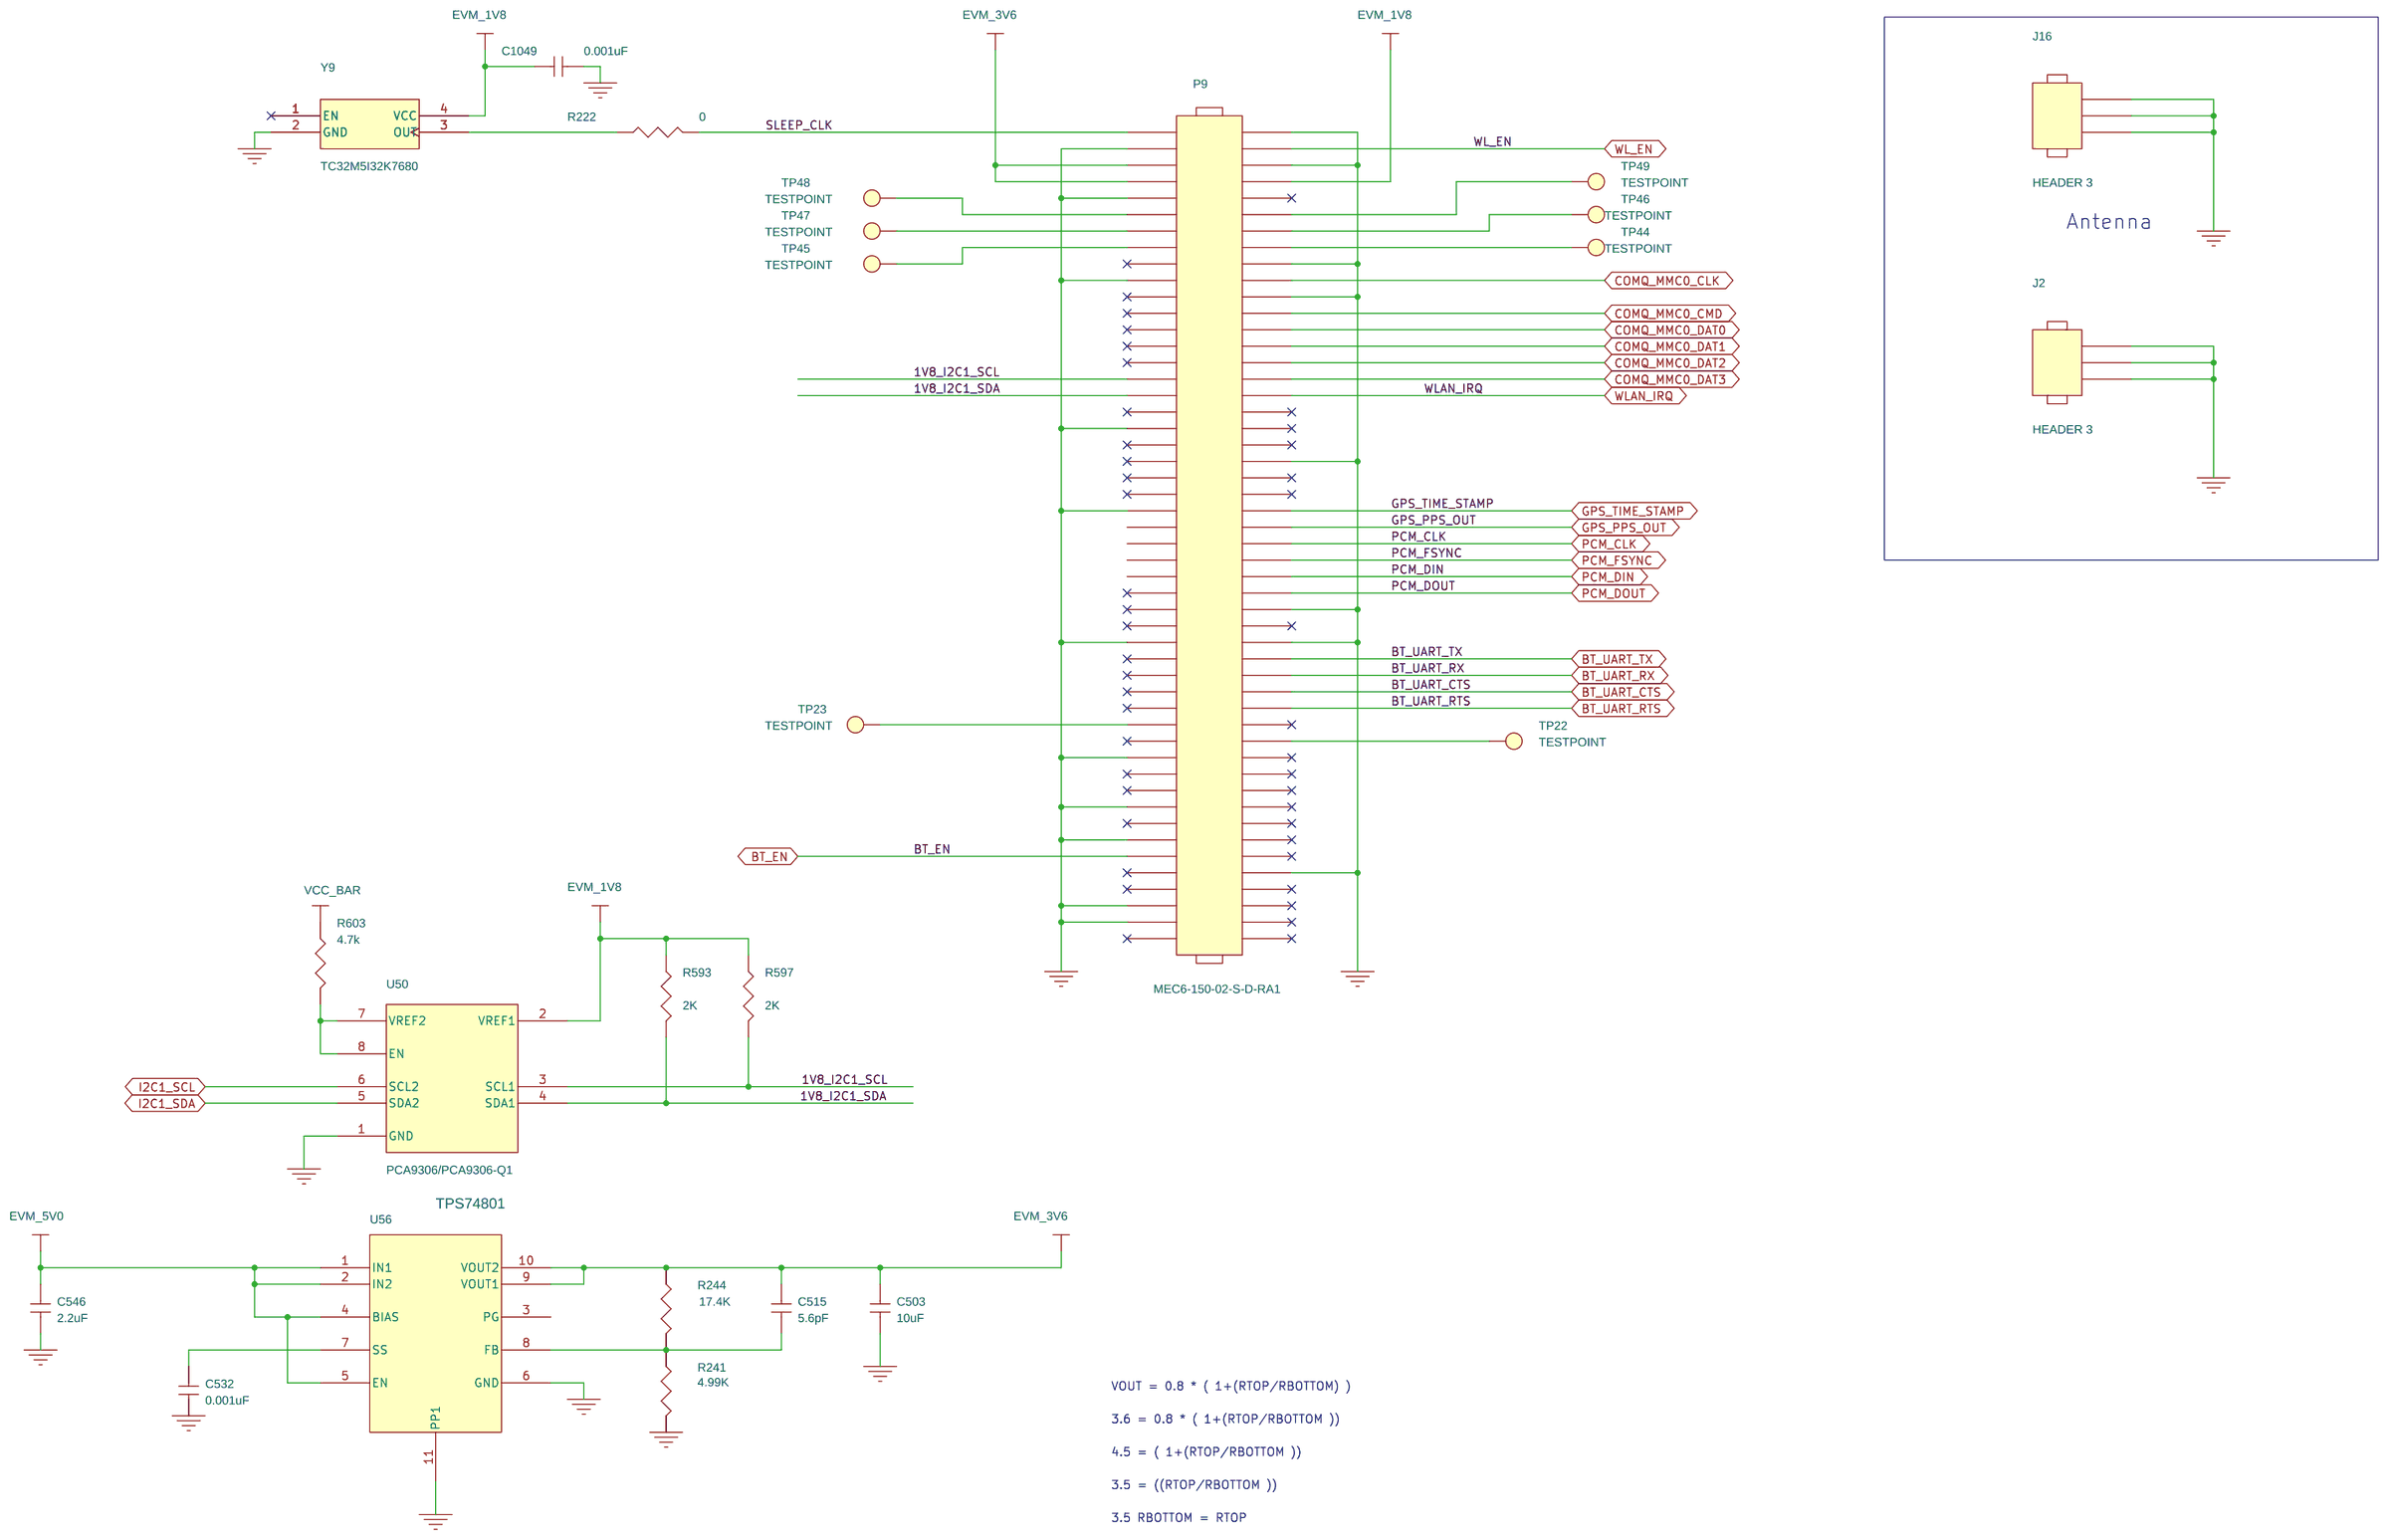
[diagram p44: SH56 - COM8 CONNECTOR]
46 SH57 - ETHERNET POWER RESET: size B; rev: C
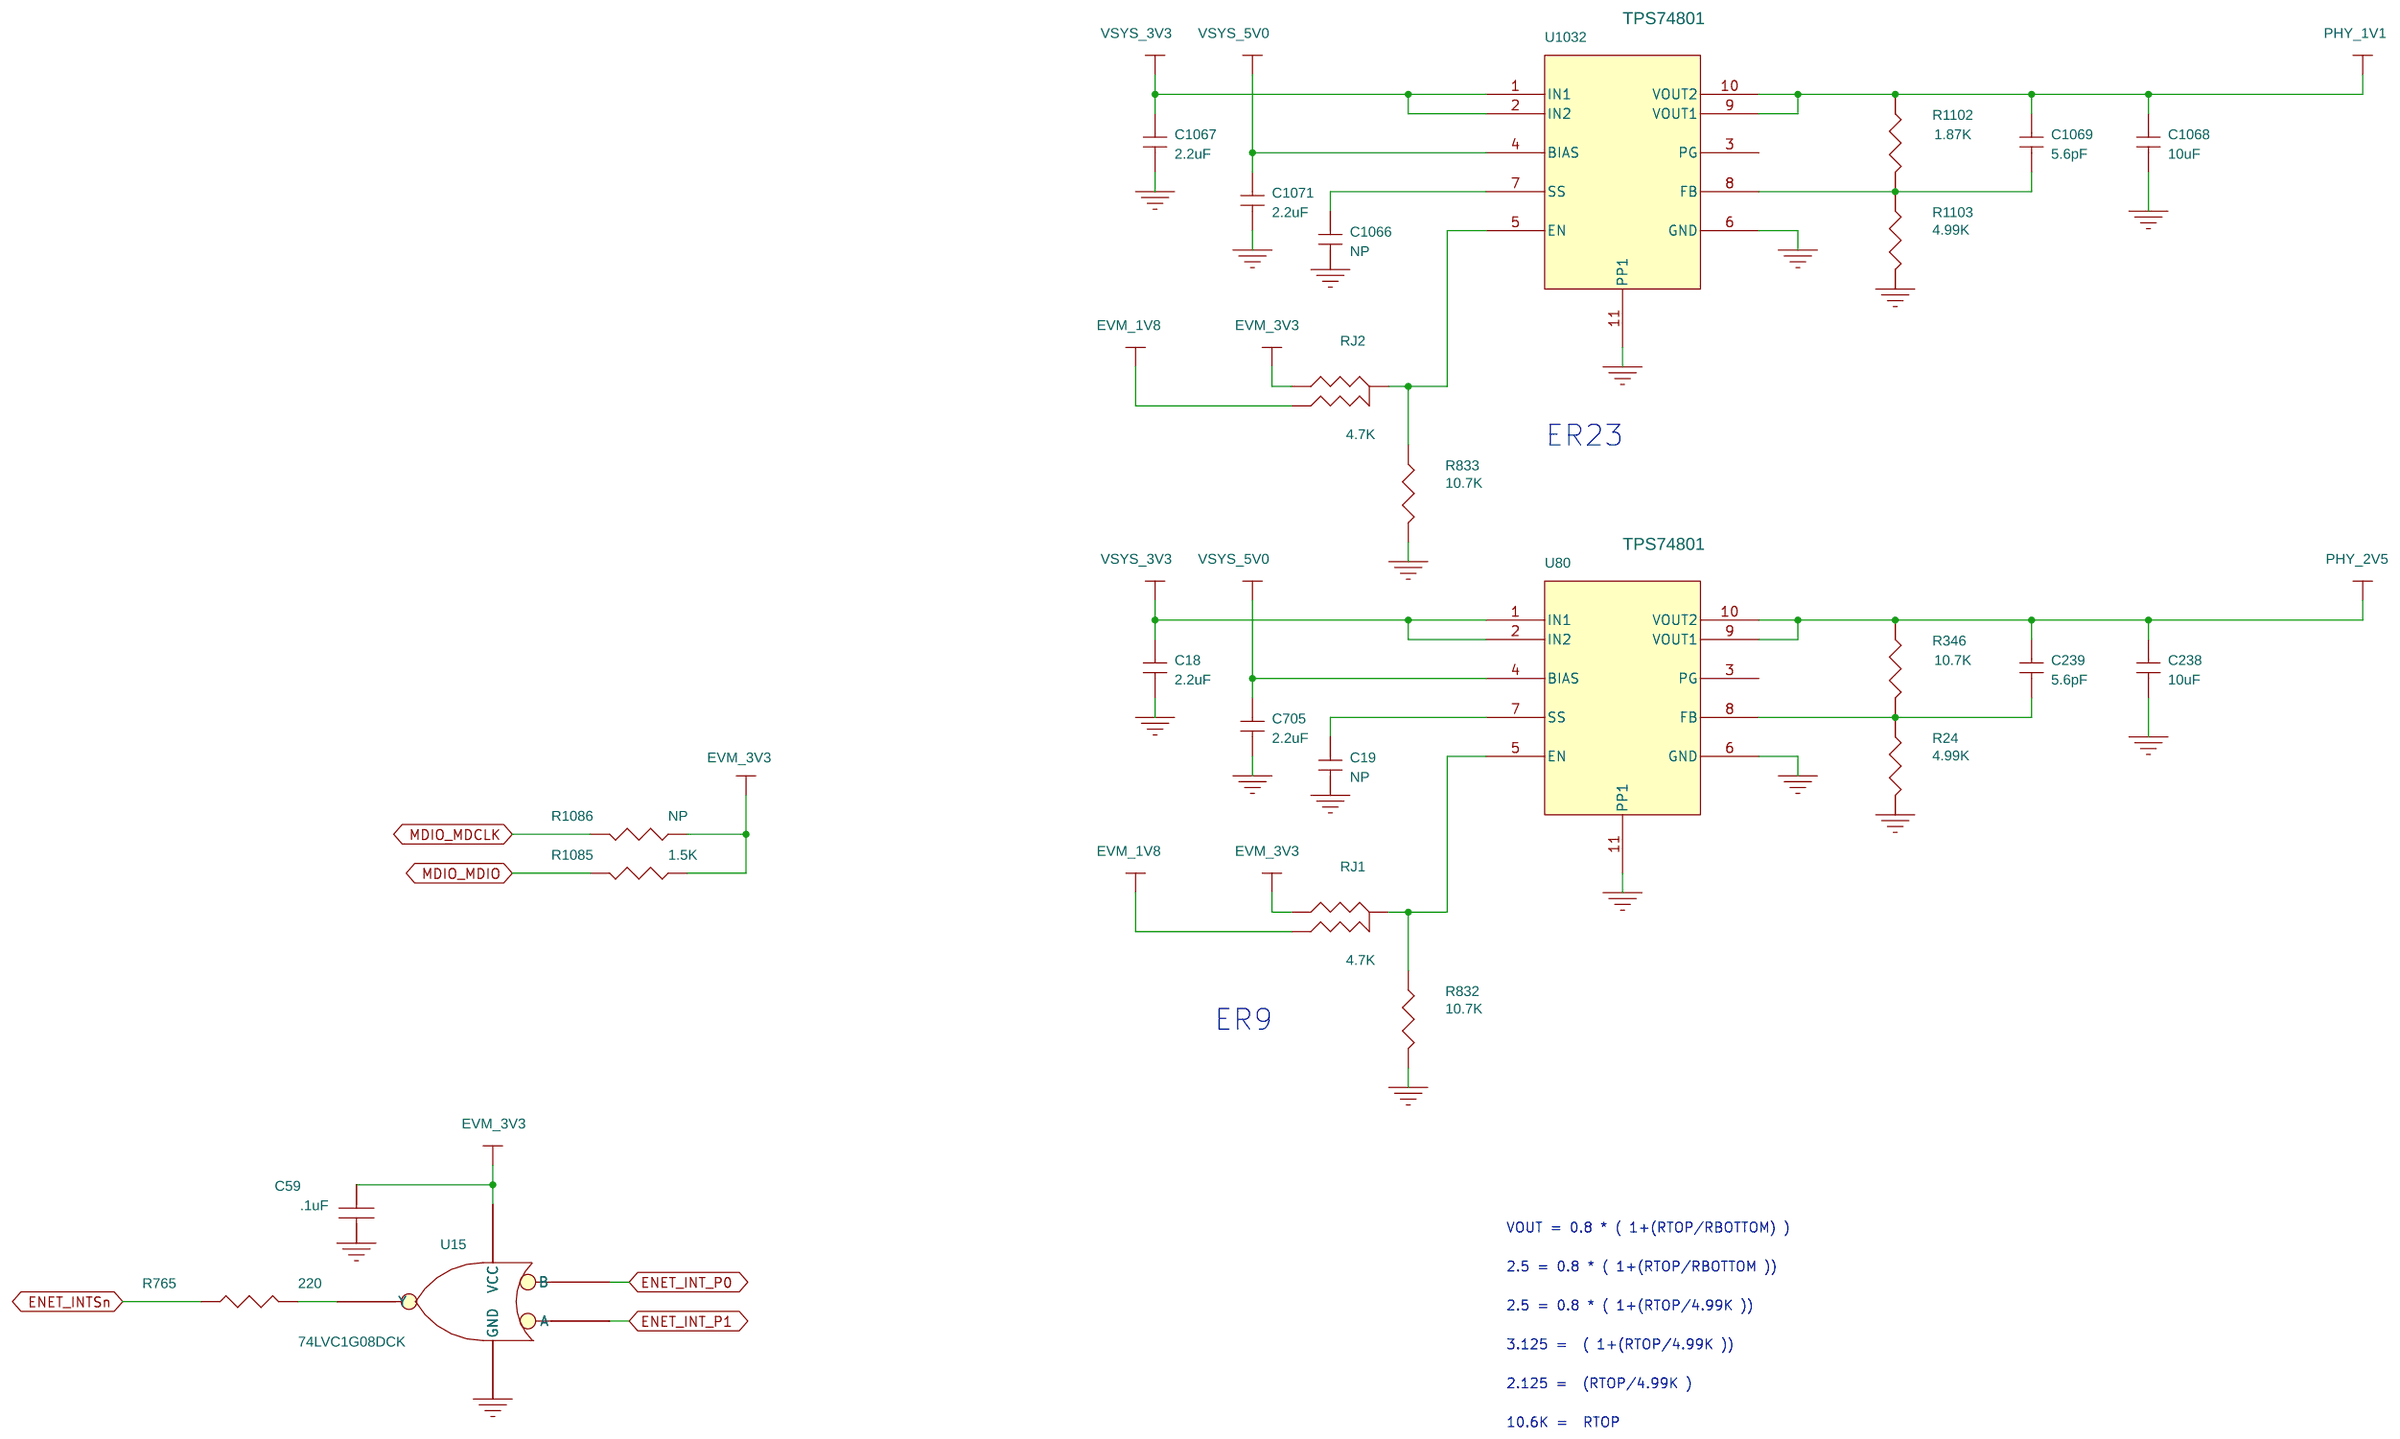
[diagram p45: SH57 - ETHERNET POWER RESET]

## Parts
sheet SH45 - SERDES CLOCK
C31  10.0uF  [c603-35x45]
C36  10.0uF  [c603-35x45]
C39  10.0uF  [c603-35x45]
C42  NO-POP  [c402-25]
C254  0.001uF  [c402-25]
C256  0.1uF  [c402-25]
C257  0.01uF  [c402-25]
C261  0.1uF  [c402-25]
C264  0.1uF  [c402-25]
C266  10.0uF  [c603-35x45]
C268  0.1uF  [c402-25]
E7  NFM21PC474R1C3D  [emi-NFM21p]
L4  Ferrite Chip  [l603-35x45]
R62  no-pop  [r402-25]
R63  10K  [r402-25]
R64  10K  [r402-25]
R65  0  [r402-25]
R70  10K  [r402-25]
R71  NO-POP  [r402-25]
R75  0  [r402-25]
TP6  TP  [tp-20RD10]
U9  CDCM9102RHBR  [QFN32_202SQ]
Y2  25.0000MHz  [xtal4-32x35-abm10]
sheet SH46 - PCIe CONNECTORS
C259  .1uF  [c603-35x45]
C262  .1uF  [c603-35x45]
C272  0.1uF  [c402-25]
C275  0.1uF  [c402-25]
C278  .1uF  [c402-25]
C279  0.1uF  [c402-25]
C288  0.1uF  [c402-25]
C291  0.1uF  [c402-25]
C292  0.1uF  [c402-25]
P7  PCIe 4X Connector  [pcie_smt_64]
R76  10K  [r402-25]
R79  NO-POP  [r402-25]
R98  1K 1%  [r402-25]
R99  10K  [r402-25]
R104  1K 1%  [r402-25]
R106  1.5K  [r402-25]
R413  10K  [r402-25]
R415  10K  [r402-25]
R416  10K  [r402-25]
R420  10K  [r402-25]
R421  10K  [r402-25]
R434  10K  [r402-25]
R439  NO-POP  [r402-25]
R448  10K  [r402-25]
RU13  74CBTLV1G125CRG4  [dck-5]
U11  74LV1G126CRG4  [dck-5]
U12  TPS3808G09DBVRG4  [DBV6-27X39-6]
U16  TPS3808G09DBVRG4  [DBV6-27X39-6]
U17  SN74LVC1G08DCKRG4  [dck-5]
sheet SH47 - LCD CONNECTOR
J15  HEADER 50  [molex-54132-50]
R636  10K  [r201-6p6spc]
R678  10K  [r402-25]
TP52  TESTPOINT  [tp-30RD13]
sheet SH48 - HDMI OUTPUT CONNECTOR
C1  0.1uF  [c402-25]
C3  0.1uF  [c402-25]
C230  0.1uF  [c402-25]
FL5  DLW21SN900HQ2  [EMI-36X15-DLW21-rdpads]
FL6  DLW21SN900HQ2  [EMI-36X15-DLW21-rdpads]
FL7  DLW21SN900HQ2  [EMI-36X15-DLW21-rdpads]
FL8  DLW21SN900HQ2  [EMI-36X15-DLW21-rdpads]
P4  HDMI-RA-19-TYPEA  [hdmi-smt-w-flange-rdpads]
R6  NP  [r402-25]
R7  NP  [r402-25]
R305  NP  [r201-6p6spc]
R321  10K  [r402-25]
R322  10K  [r402-25]
R517  NO-POP  [r201-6p6spc]
R711  NO-POP  [r201-6p6spc]
R712  NO-POP  [r201-6p6spc]
R713  NO-POP  [r201-6p6spc]
U1  TPD12S016RKTR  [rkt24]
U128  tpd1e05u06  [dpy-rdpads]
U129  tpd1e05u06  [dpy-rdpads]
U130  tpd1e05u06  [dpy-rdpads]
U131  tpd1e05u06  [dpy-rdpads]
U132  tpd1e05u06  [dpy-rdpads]
U133  tpd1e05u06  [dpy-rdpads]
U134  tpd1e05u06  [dpy-rdpads]
U135  tpd1e05u06  [dpy-rdpads]
sheet SH49 - FPD LINK
C5  0.1uF  [c402-25]
C6  0.1uF  [c402-25]
C7  4.7uF  [c603-35x45]
C8  4.7uF  [c603-35x45]
C13  4.7uF  [c603-35x45]
C215  0.1uF  [c402-25]
C216  0.1uF  [c402-25]
C228  4.7uF  [c603-35x45]
C229  4.7uF  [c603-35x45]
C231  0.1uF  [c402-25]
C232  0.1uF  [c402-25]
C234  4.7uF  [c603-35x45]
C235  4.7uF  [c603-35x45]
C236  0.1uF  [c402-25]
L2  Ferrite Chip  [l603-35x45]
L3  Ferrite Chip  [l603-35x45]
P1  D4S20D-40ML5  [con_mb261]
R8  10K  [r402-25]
R9  10K  [r402-25]
R10  10K  [r402-25]
R11  10K  [r402-25]
R20  10K  [r402-25]
R22  10K  [r402-25]
R332  10K  [r402-25]
R333  NO-POP  [r402-25]
R338  NO-POP  [r402-25]
U3  DS90UH925Q  [QFN48-11X35]
sheet SH50 - CAMERA IF
C704  .1uF  [c402-25]
C1061  0.1uF  [c402-25]
C1062  .1uF  [c402-25]
C1063  0.1uF  [c402-25]
C1064  0.1uF  [c402-25]
J5  MOLEX 052559-3679 ( mirror )  [conn36-52559-mirror]
J1002  MOLEX 052559-3679  [conn36-52559-mirror]
L1006  NP  [l805-35x60]
MHC1  MHC1  [MH93-125]
MHC2  MHC2  [MH93-125]
MHC3  MHC1  [MH93-125]
MHC4  MHC2  [MH93-125]
P15  QSH-020-01-L-D-DP-A  [qsh-020-dp-A]
R58  22  [r402-25]
R59  22  [r402-25]
R60  22  [r402-25]
R353  22  [r402-25]
R356  22  [r402-25]
R365  10K  [r402-25]
R828  10K  [r402-25]
R1055  10K  [r201-6p6spc]
R1056  10K  [r402-25]
R1058  2K  [r402-25]
R1059  2K  [r402-25]
R1060  4.7k  [r402-25]
R1062  22  [r402-25]
R1063  NP  [r402-25]
R1064  22  [r402-25]
R1065  NP  [r402-25]
R1066  22  [r402-25]
R1067  NP  [r402-25]
R1068  22  [r402-25]
R1069  NP  [r402-25]
R1070  22  [r402-25]
R1071  NP  [r402-25]
R1072  22  [r402-25]
R1073  NP  [r402-25]
R1074  22  [r402-25]
R1075  NP  [r402-25]
R1083  10K  [r402-25]
R1084  NP  [r402-25]
RN8  RPACK4-22  [rpak8-10x25-28v]
RN9  RPACK4-22  [rpak8-10x25-28v]
RN10  RPACK4-22  [rpak8-10x25-28v]
RU114  SN74CBTLV3257PW  [tssop16-14x70]
TP5  TestPoint1  [tp1-6040]
U4  NP  [OSC4-71X79]
U144  SN74LVC1G125DCKR  [dck-5]
U1029  PCA9306/PCA9306-Q1  [dcu8-10x50]
U1030  SN74AVC8T245RHL  [rhl24-pvqfn-ti]
sheet SH51 - CAN CONNECTORS
C525  4700pF  [c402-25]
C527  .1uF  [c402-25]
C531  .1uF  [c402-25]
C540  .1uF  [c402-25]
JP1  NO-POP(HEADER 3)  [JUMP1X3-6040]
JP2  HEADER 2  [JUMP1X2-6040]
JP3  HEADER 2  [JUMP1X2-6040]
R238  62  [r1206-40x70]
R255  62  [r1206-40x70]
R615  10K  [r402-25]
R617  NO-POP  [r402-25]
U54  SN65HVDA541  [so8-25x75]
U110  SN74LVC1G04DCK  [dck-5]
sheet SH53 - I2C EXPANDER
C543  .1uF  [c402-25]
C544  .1uF  [c402-25]
C691  .1uF  [c402-25]
C697  .1uF  [c402-25]
DS1  LED_GRN  [led1206-59x59]
DS2  LED_GRN  [led1206-59x59]
DS3  LED_GRN  [led1206-59x59]
DS4  LED_GRN  [led1206-59x59]
R638  0  [r402-25]
R639  NO-POP  [r402-25]
R640  NO-POP  [r402-25]
R647  10K  [r402-25]
R648  10K  [r402-25]
R649  10K  [r402-25]
R655  10K  [r402-25]
R656  10K  [r402-25]
R660  10K  [r402-25]
R661  NO-POP  [r402-25]
R662  NO-POP  [r402-25]
R663  NO-POP  [r402-25]
R665  NO-POP  [r402-25]
R666  10K  [r402-25]
R674  330  [r402-25]
R676  330  [r402-25]
R677  330  [r402-25]
R682  330  [r402-25]
R749  NO-POP  [r402-25]
R750  10K  [r402-25]
R751  NO-POP  [r402-25]
R752  10K  [r402-25]
R753  10K  [r402-25]
R754  NO-POP  [r402-25]
R785  NOPOP  [r402-25]
R786  0  [r402-25]
R789  10K  [r402-25]
R790  10K  [r402-25]
R791  10K  [r402-25]
R792  10K  [r402-25]
R793  100  [r402-25]
R794  100  [r402-25]
U57  PCF8575  [pw24-14x70]
U58  PCF8575  [pw24-14x70]
U119  PCF8575  [pw24-14x70]
U139  SN74LVC1G125DCKR  [dck-5]
U140  SN74LVC1G125DCKR  [dck-5]
sheet SH54 - BOOTSWITCHES
R80  1K  [r201-6p6spc]
R81  1K  [r201-6p6spc]
R82  1K  [r201-6p6spc]
R83  1K  [r201-6p6spc]
R84  1K  [r201-6p6spc]
R85  1K  [r201-6p6spc]
R86  1K  [r201-6p6spc]
R87  1K  [r201-6p6spc]
R88  1K  [r201-6p6spc]
R89  1K  [r201-6p6spc]
R90  1K  [r201-6p6spc]
R91  1K  [r201-6p6spc]
R92  1K  [r201-6p6spc]
R93  1K  [r201-6p6spc]
R94  1K  [r201-6p6spc]
R95  1K  [r201-6p6spc]
R110  10K  [r201-6p6spc]
R111  10K  [r201-6p6spc]
R112  10K  [r201-6p6spc]
R113  10K  [r201-6p6spc]
R114  10K  [r201-6p6spc]
R115  10K  [r201-6p6spc]
R116  10K  [r201-6p6spc]
R117  10K  [r201-6p6spc]
R118  10K  [r201-6p6spc]
R119  10K  [r201-6p6spc]
R120  10K  [r201-6p6spc]
R121  10K  [r201-6p6spc]
R122  10K  [r201-6p6spc]
R123  10K  [r201-6p6spc]
R124  10K  [r201-6p6spc]
R125  10K  [r201-6p6spc]
R201  10K  [r201-6p6spc]
R215  10K  [r201-6p6spc]
R234  10K  [r201-6p6spc]
R239  10K  [r201-6p6spc]
R383  10K  [r201-6p6spc]
R459  10K  [r201-6p6spc]
R470  10K  [r201-6p6spc]
R569  1K  [r201-6p6spc]
R579  1K  [r201-6p6spc]
R585  1K  [r201-6p6spc]
R594  1K  [r201-6p6spc]
R599  1K  [r201-6p6spc]
R601  1K  [r201-6p6spc]
R604  1K  [r201-6p6spc]
R610  1K  [r201-6p6spc]
R612  1K  [r201-6p6spc]
R619  1K  [r201-6p6spc]
R756  10K  [r201-6p6spc]
R757  10K  [r201-6p6spc]
R766  10K  [r201-6p6spc]
SW2  TDA08H0SB1R  [SW8-30X50]
SW3  TDA08H0SB1R  [SW8-30X50]
SW5  TDA10H0SK1  [SW10-30X50]
sheet SH55 - COM8 LEVEL TRANSLATOR
C331  0.1uF  [c402-25]
C332  0.1uF  [c402-25]
C335  0.1uF  [c402-25]
C344  0.1uF  [c402-25]
C345  0.1uF  [c402-25]
C351  0.1uF  [c402-25]
C404  0.1uF  [c402-25]
C405  0.1uF  [c402-25]
C411  0.1uF  [c402-25]
C448  0.1uF  [c402-25]
C472  0.1uF  [c402-25]
C479  0.1uF  [c402-25]
R157  NO-POP  [r402-25]
R178  10K  [r402-25]
R515  0  [r402-25]
R519  10K  [r402-25]
R520  10K  [r402-25]
R521  10K  [r402-25]
R522  10K  [r402-25]
R523  10K  [r402-25]
R524  10K  [r402-25]
R528  NP  [r402-25]
R558  20K  [r402-25]
R559  20K  [r402-25]
R560  20K  [r402-25]
R561  20K  [r402-25]
R562  20K  [r402-25]
R587  NO-POP  [r402-25]
R714  0  [r201-6p6spc]
R715  0  [r201-6p6spc]
U35  SN74AVC8T245RHL  [rhl24-pvqfn-ti]
U41  SN74AVC4T245RGYR  [rgy16-12x34]
U46  SN74AVC8T245RHL  [rhl24-pvqfn-ti]
U100  TXS0108EPW  [pw20-14x70]
U104  SN74LVC1T45  [DCK-17X60-6]
sheet SH56 - COM8 CONNECTOR
C503  10uF  [c603-35x45]
C515  5.6pF  [c402-25]
C532  0.001uF  [c402-25]
C546  2.2uF  [c603-35x45]
C1049  0.001uF  [c402-25]
J2  HEADER 3  [JUMP1X3-6040]
J16  HEADER 3  [JUMP1X3-6040]
P9  MEC6-150-02-S-D-RA1  [mec6-150-ra1]
R222  0  [r402-25]
R241  4.99K  [r603-35x45]
R244  17.4K  [r603-35x45]
R593  2K  [r402-25]
R597  2K  [r402-25]
R603  4.7k  [r402-25]
TP22  TESTPOINT  [tp-20RD10]
TP23  TESTPOINT  [tp-20RD10]
TP44  TESTPOINT  [tp-20RD10]
TP45  TESTPOINT  [tp-20RD10]
TP46  TESTPOINT  [tp-20RD10]
TP47  TESTPOINT  [tp-20RD10]
TP48  TESTPOINT  [tp-20RD10]
TP49  TESTPOINT  [tp-20RD10]
U50  PCA9306/PCA9306-Q1  [dcu8-10x50]
U56  TPS74801  [drc10-11x33]
Y9  TC32M5I32K7680  [xtal4-35x28]
sheet SH57 - ETHERNET POWER RESET
C18  2.2uF  [c603-35x45]
C19  NP  [c402-25]
C59  .1uF  [c402-25]
C238  10uF  [c603-35x45]
C239  5.6pF  [c402-25]
C705  2.2uF  [c603-35x45]
C1066  NP  [c402-25]
C1067  2.2uF  [c603-35x45]
C1068  10uF  [c603-35x45]
C1069  5.6pF  [c402-25]
C1071  2.2uF  [c603-35x45]
R24  4.99K  [r603-35x45]
R346  10.7K  [r603-35x45]
R765  220  [r402-25]
R832  10.7K  [r603-35x45]
R833  10.7K  [r603-35x45]
R1085  1.5K  [r402-25]
R1086  NP  [r402-25]
R1102  1.87K  [r603-35x45]
R1103  4.99K  [r603-35x45]
RJ1  4.7K  [JMP402-25]
RJ2  4.7K  [JMP402-25]
U15  74LVC1G08DCK  [dck-5]
U80  TPS74801  [drc10-11x33]
U1032  TPS74801  [drc10-11x33]

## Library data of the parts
C31 C36 C39 C266 = CAP_NP_0: Part #: 102963-0101R
C42 = CAP_NP_0: Part #: C0402-NOPOP
C254 = CAP_NP_0: Part #: 102058-1102R
C256 C261 C264 C268 = CAP_NP_0: Part #: 101587-1100R
C257 = CAP_NP_0: Part #: 101587-1101R
E7 = NFM_1: Part #: 102569-1470R
L2-L4 = FERRITE_CHIP_0: Part #: 101858-2201R
R62 R71 R79 R157 R333 R338 R439 R528 R587 R617 R639 R640 R661-R663 R665 R749 R751 R754 R1086 = R: Part #: R0402-NOPOP
R8-R11 R20 R22 R63 R64 R70 R99 R178 R321 R322 R332 R365 R415 R416 R421 R434 R448 R519-R524 R615 R647-R649 R655 R656 R660 R666 R678 R750 R752 R753 R789-R792 R828 R1056 R1083 = R: Part #: 101370-1003R
R65 R75 R222 R515 R638 R786 = R: Part #: 101370-0001R
TP6 = TP_0: Part #: TP-20RD10-NO-POP
U9 = CDCM9102RHBR_2: Part #: 104237-0001R
Y2 = CRYSTAL_4-PIN_0: Part #: 103419-0250R
C259 C262 = CAP_.1_uF_10%_0603: Part #: 100994-1100R
C272 C291 C1062 = CAP_NP_1: Part #: 101587-1100R
C59 C275 C278 C279 C288 C292 = CAP_NP_2: Part #: 101587-1100R
P7 = PCI_Connector_0: Part #: 103341-0001R
R76 R413 = RESISTOR: Part #: 101370-1003R
R98 R104 = R_2: Part #: 102145-1002R
R106 R1085 = R: Part #: 101370-1502R
R420 = R_2: Part #: 101370-1003R
RU13 = SN74LVC1G125: Part #: 101689-0125R
U11 = SN74LVC1G125_0: Part #: 101057-0126R
U12 U16 = TPS3808G09DBVR_0: Part #: 102020-0009R
U15 U17 = 1G08: Part #: 101057-0008R
J15 = HEADER_50: Part #: 103716-0050R
R201 R215 R234 R239 R383 R459 R470 R636 R756 R757 R766 R1055 = R: Part #: 103158-1003R
TP52 = TESTPOINT: Part #: TP-30RD13-NO-POP
C1 C3 C230 C405 C411 C543 C544 C691 C697 C704 C1061 C1063 C1064 = CAP_NP: Part #: 101587-1100R
FL5-FL8 = DLW21SN900HQ2: Part #: 104184-9000R
P4 = HDMI-RA-19_0: Part #: 103169-0001R
R6 R7 R785 = R: Part #: r0402-nopop
R305 = R: Part #: r0201-nopop
R517 R711-R713 = R: Part #: R0201-NOPOP
U1 = TPD12S016RKTR_QFN24_3: Part #: 103797-0001R
U128-U135 = tpd1e05u06: Part #: 104410-0001R
C5 C6 C231 C232 C236 C331 C332 C335 C344 C345 C351 C404 C448 C472 C479 C527 C531 C540 = CAP: Part #: 101587-1100R
C7 C8 C13 C228 C229 C234 C235 = CAP: Part #: 102590-0470R
C215 C216 = CAP_0603: Part #: 101587-1100R
P1 = D4S20D-40ML5-Y: Part #: 104234-0001R
U3 = DS90UH925Q_1: Part #: 104304-0001R
J5 J1002 = HEADER_36: Part #: 103723-0036R
L1006 = INDUCTOR_0: Part #: NO-POP
MHC1-MHC4 = TESTPOINT: Part #: no-pop
P15 = QSH-020-01-L-D-DP-A: Part #: 103429-0020R
R58 R59 R353 = R: Part #: 101370-2200R
R60 R356 R1062 R1064 R1066 R1068 R1070 R1072 R1074 = R_1: Part #: 101370-2200R
R593 R597 R1058 R1059 = RESISTOR_0: Part #: 102145-2002R
R603 R1060 = RESISTOR_0: Part #: 101370-4702R
R1063 R1065 R1067 R1069 R1071 R1073 R1075 R1084 = R_1: Part #: R0402-NOPOP
RN8-RN10 = R-Pak4_0: Part #: 101327-2200R
RU114 = SN74CBT3257PW_0: Part #: 101670-0001R
TP5 = TestPoint1_0: Part #: 100115-0001R
U4 = OSC4_SM_0: Part #: NO-POP; SD PCB Footprint: CB3LV
U139 U140 U144 = SN74LVC1G125: Part #: 101057-0125R
U50 U1029 = PCA9306: Part #: 103282-0001R
U35 U46 U1030 = SN74AVC8T245_1: Part #: 102708-0001R
C525 = CAP: Part #: 103217-1472R
JP1 = HEADER_3: Part #: NO-POP
JP2 JP3 = HEADER_2: Part #: 100115-0002R
R238 R255 = R: Part #: 100155-6200R
U54 = SN65HVDA541: Part #: 103628-0001R
U110 = SN74LVC1GU04_1: Part #: 101057-0004R
DS1-DS3 = LED_0: Part #: 100823-0001R
DS4 = LED_RED_0: Part #: 100823-0001R
R674 R676 R677 R682 = R_0: Part #: 101370-3301R
R793 R794 = R_0: Part #: 101370-1001R
U57 U58 U119 = PCF8575_1: Part #: 102385-0001R
R80-R95 R569 R579 R585 R594 R599 R601 R604 R610 R612 R619 = R_1: Part #: 103158-1002R
R110-R125 = R_1: Part #: 103158-1003R
SW2 SW3 = SW_DIP-8: Part #: 101184-0008R
SW5 = DIP_SWITCH_10: 10POS Dip Switch Half Pitch SMT; Comment: DIP_SWITCH-10; Mfgr: C & K; Part #: 101184-0010R; Vendor: Digi-Key; Vendor Nbr: CKN1366-ND
R558-R562 = R: Part #: 101370-2003R
R714 R715 = R: Part #: 103158-0001R
U41 = SN74AVC4T245RGYR_0: Part #: 102649-0245R
U100 = TXB0108PWR_0: Part #: 103666-0001R
U104 = TMP_1: Part #: 102156-0001R
C238 C503 C1068 = CAP_NP: Part #: 102963-0101R
C239 C515 C1069 = Cap_100nF_Cermc_16V_10%_603_3: Part #: 101782-1565R
C532 C1049 = CAP_NP: Part #: 102058-1102R
C18 C546 C705 C1067 C1071 = CAP_NP: Part #: 101007-0220R
J2 J16 = HEADER_3: Part #: 100115-0003R
P9 = HEADER_50x2: Part #: 103626-0050R
R24 R241 R1103 = R_3: Part #: 100642-4992R
R244 = R_3: Part #: 100642-1743R
TP22 TP23 TP44-TP49 = TESTPOINT: Part #: TP-20RD10-NO-POP
U56 U80 U1032 = U-TPS78601_AJUST_-_1_3.5A_LDO: Part #: 104335-0001R
Y9 = OSC4_SM_0_v2: Part #: 104441-3276R
C19 C1066 = CAP_NP: Part #: c0402-nopop
R346 R832 R833 = R_3: Part #: 100642-1073R
R765 = R: Part #: 101370-2201R
R1102 = R_3: Part #: 100642-1873R
RJ1 RJ2 = RJUMP3: Part #: 101370-4702R

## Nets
1V8_I2C1_SCL: P9.31 R597.2 U50.3(SCL1)
1V8_I2C1_SDA: P9.33 R593.2 U50.4(SDA1)
3V3_REF_CLK: R1075.1 R1083.1 U4.3(OUT) U1030.10(A8)
3V3_SPI[1]_CS[0]n: R1056.1 R1063.1 RU114.2(1B1) U1030.3(A1)
3V3_SPI[1]_MOSI: R1065.1 RU114.14(4B1) U1030.5(A3)
3V3_SPI[1]_SCLK: R1067.1 RU114.11(3B1) U1030.4(A2)
3V3_VDDA: C31.1 C254.1 C256.1 C257.1 L4.2 R63.1 R64.1 R70.1 U9.9(VDD3) U9.16(VDD4) U9.18(VDD5) U9.20(VDD6)
GND: C1.2 C3.2 C7.2 C8.2 C13.2 C18.2 C19.2 C31.2 C36.2 C39.2 C59.2 C215.1 C216.2 C228.2 C229.2 C230.2 C231.2 C232.2 C234.2 C235.2 C236.2 C238.2 C254.2 C256.2 C257.2 C261.2 C264.2 C266.2 C268.2 C272.2 C275.2 C278.2 C279.2 C288.2 C291.2 C292.2 C331.2 C332.2 C335.2 C344.2 C345.2 C351.2 C404.2 C405.2 C411.2 C448.2 C472.2 C479.2 C503.2 C525.2 C527.2 C531.2 C532.2 C540.2 C543.1 C544.1 C546.2 C691.1 C697.1 C704.1 C705.2 C1049.2 C1061.1 C1062.2 C1063.1 C1064.2 C1066.2 C1067.2 C1068.2 C1071.2 E7.2 J2.1 J2.2 J2.3 J5.6 J5.8 J5.10 J5.25 J5.26 J15.13 J15.18 J15.27 J15.36 J15.45 J15.50 J16.1 J16.2 J16.3 J1002.6 J1002.7 J1002.10 J1002.13 J1002.16 J1002.19 J1002.22 J1002.29 J1002.33 J1002.34 JP1.2 P1.SH1 P1.SH2 P1.SH3 P1.SH4 P4.2(D2_SHIELD) P4.5(D1_SHIELD) P4.8(D0_SHIELD) P4.11(CK_SHIELD) P4.17(GND) P4.MTG1 P4.MTG2 P4.MTG3 P4.MTG4 P7.A4(GND.12) P7.A12(GND.13) P7.A15(GND.14) P7.A18(GND.15) P7.A20(GND.16) P7.A23(GND.17) P7.A24(GND.18) P7.A27(GND.19) P7.A28(GND.20) P7.A31(GND.21) P7.B4(GND.1) P7.B7(GND.2) P7.B13(GND.3) P7.B16(GND.4) P7.B18(GND.5) P7.B21(GND.6) P7.B22(GND.7) P7.B25(GND.8) P7.B26(GND.9) P7.B29(GND.10) P7.B32(GND.11) P9.2 P9.3 P9.6 P9.9 P9.18 P9.19 P9.22 P9.37 P9.42 P9.47 P9.60 P9.63 P9.64 P9.77 P9.83 P9.87 P9.92 P9.95 P9.97 P15.12 P15.16 P15.24 P15.41(SH_GND.1) P15.42(SH_GND.2) P15.43(SH_GND.4) P15.44(SH_GND.3) R9.2 R10.2 R11.2 R24.2 R62.2 R65.2 R71.2 R75.2 R98.1 R104.1 R110.2 R111.2 R112.2 R113.2 R114.2 R115.2 R116.2 R117.2 R118.2 R119.2 R120.2 R121.2 R122.2 R123.2 R124.2 R125.2 R157.2 R178.2 R241.2 R305.2 R333.2 R338.2 R421.2 R448.2 R515.2 R569.1 R579.1 R585.1 R594.1 R599.1 R601.1 R604.1 R610.1 R612.1 R615.2 R617.2 R619.1 R636.2 R648.2 R649.2 R655.2 R656.2 R660.2 R661.2 R714.1 R715.2 R749.2 R751.2 R752.2 R832.2 R833.2 R1103.2 RU13.3(GND) RU114.8(GND) RU114.15(~{OE}) U1.5(GND1) U1.13(GND2) U1.18(GND3) U3.15(RES0) U3.18(RES1) U3.49(DAP(PWRPAD)) U4.2(GND) U9.14(GND.1) U9.22(GND.2) U9.33(PWR_PAD) U11.3(GND) U12.2(GND) U15.3(GND) U16.2(GND) U17.3(GND) U35.2(DIR) U35.11(GND) U35.12(GND) U35.13(GND) U35.25(PP) U41.7(2A2) U41.8(GND.1) U41.9(GND.2) U41.17(GND.3) U46.11(GND) U46.12(GND) U46.13(GND) U46.25(PP) U50.1(GND) U54.2(GND) U56.6(GND) U56.11(PP1) U57.12(GND) U58.12(GND) U80.6(GND) U80.11(PP1) U100.11(GND1) U100.17(B3) U100.18(B2) U100.20(B1) U104.2(GND) U104.5(DIR) U110.3(GND) U119.12(GND) U128.2(GND) U129.2(GND) U130.2(GND) U131.2(GND) U132.2(GND) U133.2(GND) U134.2(GND) U135.2(GND) U139.3(GND) U140.3(GND) U144.2(I) U144.3(GND) U1029.1(GND) U1030.6(A4) U1030.7(A5) U1030.8(A6) U1030.11(GND) U1030.12(GND) U1030.13(GND) U1030.22(OEn) U1030.25(PP) U1032.6(GND) U1032.11(PP1) Y2.2(GND1) Y2.4(GND2) Y9.2(GND) ; also on sheet 3 5 7 10 11 12 13 14 15 16 17 18 20 21 22 23 24 25 26 27 28 29 30 31 32 33 34 47 48 49 50 51 52 53 54 55 56 57 58 59 62 63 64 65 66 67 68 69 70 71
VDD_CDCM9102: C261.1 C264.1 C266.1 C268.1 E7.3 U9.1(VDD2_OUT1) U9.4(VDD1_OUT0)
VIN2_S0: U119.6(P2) ; also on sheet 25
VIN2_S2: U119.10(P6) ; also on sheet 25
VIN6_SEL_S0: U119.5(P1) ; also on sheet 66
BT_EN: P9.89 U46.20(B2)
BT_UART_CTS: P9.70 U46.15(B7)
BT_UART_RTS: P9.72 U35.16(B6)
BT_UART_RX: P9.68 U46.14(B8)
BT_UART_TX: P9.66 U35.17(B5)
C_CSI2_0_DX0: J1002.8 P15.5 ; also on sheet 9
C_CSI2_0_DX1: J1002.11 P15.9 ; also on sheet 9
C_CSI2_0_DX2: J1002.14 P15.13 ; also on sheet 9
C_CSI2_0_DX3: J1002.17 P15.17 ; also on sheet 9
C_CSI2_0_DX4: J1002.20 P15.21 ; also on sheet 9
C_CSI2_0_DY0: J1002.9 P15.7 ; also on sheet 9
C_CSI2_0_DY1: J1002.12 P15.11 ; also on sheet 9
C_CSI2_0_DY2: J1002.15 P15.15 ; also on sheet 9
C_CSI2_0_DY3: J1002.18 P15.19 ; also on sheet 9
C_CSI2_0_DY4: J1002.21 P15.23 ; also on sheet 9
C_CSI2_1_DX0: P15.25 ; also on sheet 9
C_CSI2_1_DX1: P15.29 ; also on sheet 9
C_CSI2_1_DX2: P15.33 ; also on sheet 9
C_CSI2_1_DY0: P15.27 ; also on sheet 9
C_CSI2_1_DY1: P15.31 ; also on sheet 9
C_CSI2_1_DY2: P15.35 ; also on sheet 9
CAM_SPI[1]_CS[0]n: RU114.4(1A) ; also on sheet 62
CAM_SPI[1]_MISO: RU114.7(2A) ; also on sheet 62
CAM_SPI[1]_MOSI: RU114.12(4A) ; also on sheet 62
CAM_SPI[1]_SCLK: RU114.9(3A) ; also on sheet 62
CAMERA_CLK: R58.1 ; also on sheet 25
CAMERA_D0: R356.1 ; also on sheet 25
CAMERA_D1: R60.1 ; also on sheet 25
CAMERA_D2: RN8.5(R4B) ; also on sheet 25
CAMERA_D3: RN8.6(R3B) ; also on sheet 25
CAMERA_D4: RN8.7(R2B) ; also on sheet 25
CAMERA_D5: RN8.8(R1B) ; also on sheet 25
CAMERA_D6: RN9.5(R4B) ; also on sheet 25
CAMERA_D7: RN9.6(R3B) ; also on sheet 25
CAMERA_D8: RN9.7(R2B) ; also on sheet 25
CAMERA_D9: RN9.8(R1B) ; also on sheet 25
CAMERA_D10: RN10.5(R4B) ; also on sheet 25
CAMERA_D11: RN10.6(R3B) ; also on sheet 25
CAMERA_D12: RN10.7(R2B) ; also on sheet 25
CAMERA_D13: RN10.8(R1B) ; also on sheet 25
CAMERA_HSYNC: R353.1 ; also on sheet 25
CAMERA_VSYNC: R59.1 ; also on sheet 25
COMQ_MMC0_CLK: P9.20 U104.3(A)
COMQ_MMC0_CMD: P9.24 R559.2 U100.5(A4)
COMQ_MMC0_DAT0: P9.26 R560.2 U100.6(A5)
COMQ_MMC0_DAT1: P9.28 R561.2 U100.7(A6)
COMQ_MMC0_DAT2: P9.30 R562.2 U100.8(A7)
COMQ_MMC0_DAT3: P9.32 R558.2 U100.9(A8)
CON.PCIE_RXN0: P7.A17(PERn0) ; also on sheet 71
CON.PCIE_RXN1: P7.A22(PERn1) ; also on sheet 32
CON.PCIE_RXP0: P7.A16(PERp0) ; also on sheet 71
CON.PCIE_RXP1: P7.A21(PERp1) ; also on sheet 32
CON.PCIE_TXN0: P7.B15(PETn0) ; also on sheet 71
CON.PCIE_TXN1: P7.B20(PETn1) ; also on sheet 32
CON.PCIE_TXP0: P7.B14(PETp0) ; also on sheet 71
CON.PCIE_TXP1: P7.B19(PETp1) ; also on sheet 32
CON_LCD_PWR_DN: J15.14 R678.2 U58.18(P15)
CPU_HDMI_TX0+: FL7.1 ; also on sheet 7
CPU_HDMI_TX0-: FL7.4 ; also on sheet 7
CPU_HDMI_TX1+: FL6.1 ; also on sheet 7
CPU_HDMI_TX1-: FL6.4 ; also on sheet 7
CPU_HDMI_TX2+: FL5.1 ; also on sheet 7
CPU_HDMI_TX2-: FL5.4 ; also on sheet 7
CPU_HDMI_TXC+: FL8.1 ; also on sheet 7
CPU_HDMI_TXC-: FL8.4 ; also on sheet 7
CSI2_I2C_SCL: J1002.25 R1058.2 R1068.1 U1029.3(SCL1)
CSI2_I2C_SDA: J1002.24 R1059.2 R1070.1 U1029.4(SDA1)
CSI2_REF_CLK: R1074.1 R1084.1 U1030.14(B8)
CSI2_RESETn: J1002.23 R1072.1 U1030.15(B7)
CSI2_SPI[1]_CS[0]n: J1002.32 R1062.1 U1030.21(B1)
CSI2_SPI[1]_MOSI: J1002.30 R1064.1 U1030.19(B3)
CSI2_SPI[1]_SCLK: J1002.31 R1066.1 U1030.20(B2)
DCAN1_RX: JP2.2 U54.4(RXD) ; also on sheet 11
DCAN1_TX: JP2.1 R617.1 U54.1(TXD) ; also on sheet 62
DCAN2_RX: JP3.2 ; also on sheet 67
DCAN2_TX: JP3.1 ; also on sheet 67
ENET_INT_P0: U15.1(B) ; also on sheet 47
ENET_INT_P1: U15.2(A) ; also on sheet 48
ENET_INTSn: R765.1 ; also on sheet 62
EVM_1V8: C332.1 C335.1 C345.1 C405.1 C411.1 C448.1 C472.1 C1049.1 C1064.1 J15.7 J15.8 J1002.4 J1002.5 P9.8 P15.38 P15.40 R558.1 R559.1 R560.1 R561.1 R562.1 R593.1 R597.1 R1058.1 R1059.1 RJ1.3 RJ2.3 U35.23(VCCB) U35.24(VCCB) U41.16(VCCB) U46.23(VCCB) U46.24(VCCB) U50.2(VREF1) U100.2(VCCA) U100.10(OE) U104.1(VCCA) U1029.2(VREF1) U1030.23(VCCB) U1030.24(VCCB) Y9.4(VCC) ; also on sheet 29 50 55 57 59
EVM_3V3: C1.1 C59.1 C272.1 C278.1 C291.1 C331.1 C344.1 C351.1 C404.1 C479.1 C543.2 C544.2 C691.2 C697.2 C704.2 C1061.2 C1063.2 E7.1 J5.1 J5.2 J5.3 J15.4 J15.5 J15.6 J1002.1 J1002.2 J1002.3 L2.2 L3.1 L4.1 L1006.2 P15.30 P15.32 P15.34 P15.36 R6.2 R7.2 R8.1 R20.1 R22.1 R76.2 R80.1 R81.1 R82.1 R83.1 R84.1 R85.1 R86.1 R87.1 R88.1 R89.1 R90.1 R91.1 R92.1 R93.1 R94.1 R95.1 R106.1 R201.1 R215.1 R234.1 R239.1 R321.1 R322.1 R332.1 R365.2 R383.1 R413.2 R415.1 R416.1 R420.2 R434.1 R459.1 R470.1 R517.2 R519.1 R520.1 R521.1 R522.1 R523.1 R524.1 R528.1 R587.1 R603.1 R639.1 R640.1 R647.1 R662.1 R663.1 R665.1 R666.1 R674.1 R676.1 R677.1 R678.1 R682.1 R750.1 R753.1 R754.1 R756.1 R757.1 R766.1 R789.1 R790.1 R791.1 R792.1 R828.2 R1055.1 R1056.2 R1060.1 R1083.2 R1085.1 R1086.1 RJ1.1 RJ2.1 RU13.5(VCC) RU114.16(VCC) U1.23(VCCA) U4.1(EN) U11.5(VCC) U15.5(VCC) U17.5(VCC) U35.1(VCCA) U41.1(VCCA) U46.1(VCCA) U46.2(DIR) U57.24(VDD) U58.24(VDD) U100.19(VCCB) U104.6(VCCB) U119.24(VDD) U139.5(VCC) U140.5(VCC) U144.5(VCC) U1030.1(VCCA) U1030.2(DIR) ; also on sheet 3 4 10 11 24 25 26 27 28 29 30 31 32 33 34 47 48 49 50 51 55 56 58 59 62 63 65 66 67 69 70
EVM_3V6: C503.1 C515.1 P9.5 P9.7 R244.1 U56.9(VOUT1) U56.10(VOUT2)
EVM_5V0: C230.1 C275.1 C288.1 C531.1 C546.1 J5.4 J5.5 J15.1 J15.2 J15.3 R711.2 R712.2 R713.1 U1.10(VCC5V) U12.6(VDD) U16.6(VDD) U54.3(VCC) U56.1(IN1) U56.2(IN2) U56.4(BIAS) U56.5(EN) ; also on sheet 25 30 31 50 54 55 58 63 68
EVM_12V: P7.A2(+12V.4) P7.A3(+12V.5) P7.B1(+12V.1) P7.B2(+12V.2) P7.B3(+12V.3) R99.1 ; also on sheet 3 50 53 54 58
EXP_ETH0_RSTn: U58.13(P10) ; also on sheet 47
EXP_ETH1_RSTn: U58.14(P11) ; also on sheet 48
EXVIN2_S0: U119.14(P11) ; also on sheet 25
EXVIN2_S2: U119.15(P12) ; also on sheet 25
FPD_DOUT+: C5.2 P1.3
FPD_DOUT-: C6.2 P1.1
GP5[4]: U46.4(A2) ; also on sheet 2
GP5[5]: U35.5(A3) ; also on sheet 2
GP5[6]: U46.6(A4) ; also on sheet 2
GP5[7]: U35.3(A1) ; also on sheet 2
GP5[8]: U46.5(A3) ; also on sheet 2
GPMC_D00: R110.1 SW2.1(A1) ; also on sheet 27 28 59 63
GPMC_D01: R111.1 SW2.2(A2) ; also on sheet 27 28 59 63
GPMC_D02: R112.1 SW2.3(A3) ; also on sheet 27 28 59 63
GPMC_D03: R113.1 SW2.4(A4) ; also on sheet 27 28 59 63
GPMC_D04: R114.1 SW2.5(A5) ; also on sheet 27 28 59 63
GPMC_D05: R115.1 SW2.6(A6) ; also on sheet 27 28 59 63
GPMC_D06: R116.1 SW2.7(A7) ; also on sheet 27 28 63
GPMC_D07: R117.1 SW2.8(A8) ; also on sheet 27 28 63
GPMC_D08: R118.1 SW3.1(A1) ; also on sheet 27 28 63
GPMC_D09: R119.1 SW3.2(A2) ; also on sheet 27 28 63
GPMC_D10: R120.1 SW3.3(A3) ; also on sheet 27 28 63
GPMC_D11: R121.1 SW3.4(A4) ; also on sheet 27 28 63
GPMC_D12: R122.1 SW3.5(A5) ; also on sheet 27 28 63
GPMC_D13: R123.1 SW3.6(A6) ; also on sheet 27 28 63
GPMC_D14: R124.1 SW3.7(A7) ; also on sheet 27 28 63
GPMC_D15: R125.1 SW3.8(A8) ; also on sheet 27 28 63
GPMC_WPN: R756.2 SW5.12 ; also on sheet 27
GPS_PPS_OUT: P9.50 U35.19(B3)
GPS_TIME_STAMP: P9.48 U46.18(B4)
HDMI_CEC_A: U1.24(CEC_A) ; also on sheet 62
HDMI_CEC_B: P4.13(CE_REMOTE) R517.1 U1.6(CEC_B)
HDMI_CT_HPD: R322.2 U1.11(CT_HPD) U119.8(P4)
HDMI_DSCL: R7.1 U1.1(SCL_A) ; also on sheet 62
HDMI_DSDA: R6.1 U1.2(SDA_A) ; also on sheet 62
HDMI_HPD: U1.3(HPD_A) ; also on sheet 62
HDMI_HPD_B: P4.19(HP_DET) R305.1 R713.2 U1.9(HPD_B)
HDMI_LS_OE: R321.2 U1.4(LS_OE) U119.9(P5)
HDMI_SCL_B: P4.15(DDC_CLK) R711.1 U1.7(SCL_B)
HDMI_SDA_B: P4.16(DDC_DATA) R712.1 U1.8(SDA_B)
HDMI_TX0+: FL7.2 P4.7(D0+) U132.1(IO)
HDMI_TX0-: FL7.3 P4.9(D0-) U133.1(IO)
HDMI_TX1+: FL6.2 P4.4(D1+) U130.1(IO)
HDMI_TX1-: FL6.3 P4.6(D1-) U131.1(IO)
HDMI_TX2+: FL5.2 P4.1(D2+) U128.1(IO)
HDMI_TX2-: FL5.3 P4.3(D2-) U129.1(IO)
HDMI_TXC+: FL8.2 P4.10(CK+) U134.1(IO)
HDMI_TXC-: FL8.3 P4.12(CK-) U135.1(IO)
I2C1_SCL: J15.17 U50.6(SCL2) U57.22(SCL) U58.22(SCL) ; also on sheet 3 34 50 56 62 69
I2C1_SDA: J15.16 U50.5(SDA2) U57.23(SDA) U58.23(SDA) ; also on sheet 3 34 50 56 62 69
I2C5_SCL: J5.29 R1069.1 U3.8(SCL) U119.22(SCL) U1029.6(SCL2) ; also on sheet 51 66
I2C5_SDA: J5.30 R1071.1 U3.9(SDA) U119.23(SDA) U1029.5(SDA2) ; also on sheet 51 66
I2C_EEPROM_WP: R757.2 SW5.11 ; also on sheet 69
J6_VDDSHV5: C527.1 C540.1 U54.5(VIO/NC) U110.5(VCC) ; also on sheet 11 13 58 59
LCD_B0: J15.37 ; also on sheet 8
LCD_B1: J15.38 ; also on sheet 8
LCD_B2: J15.39 ; also on sheet 8 10
LCD_B3: J15.40 ; also on sheet 8 10
LCD_B4: J15.41 ; also on sheet 8 10
LCD_B5: J15.42 ; also on sheet 8 10
LCD_B6: J15.43 ; also on sheet 8 10
LCD_B7: J15.44 ; also on sheet 8 10
LCD_DE: J15.46 ; also on sheet 8
LCD_G0: J15.28 ; also on sheet 8
LCD_G1: J15.29 ; also on sheet 8
LCD_G2: J15.30 ; also on sheet 8 10
LCD_G3: J15.31 ; also on sheet 8 10
LCD_G4: J15.32 ; also on sheet 8 10
LCD_G5: J15.33 ; also on sheet 8 10
LCD_G6: J15.34 ; also on sheet 8 10
LCD_G7: J15.35 ; also on sheet 8 10
LCD_HS: J15.47 ; also on sheet 8
LCD_PCLK: J15.49 ; also on sheet 8
LCD_R0: J15.19 ; also on sheet 8
LCD_R1: J15.20 ; also on sheet 8
LCD_R2: J15.21 ; also on sheet 8 10
LCD_R3: J15.22 ; also on sheet 8 10
LCD_R4: J15.23 ; also on sheet 8 10
LCD_R5: J15.24 ; also on sheet 8 10
LCD_R6: J15.25 ; also on sheet 8 10
LCD_R7: J15.26 ; also on sheet 8 10
LCD_VS: J15.48 ; also on sheet 8
LPD_SPI[1]_CS[0]n: J5.34 R365.1 RU114.3(1B2)
LPD_SPI[1]_MISO: J5.31 RU114.6(2B2)
LPD_SPI[1]_MOSI: J5.36 RU114.13(4B2)
LPD_SPI[1]_SCLK: J5.32 RU114.10(3B2)
MCA7_AXR0: U35.9(A7) ; also on sheet 66
MCA7_AXR1: U41.6(2A1) ; also on sheet 66
MCA7_CLKX: U41.4(1A1) ; also on sheet 66
MCA7_FSX: U41.5(1A2) ; also on sheet 66
MCASP1_ENn: R766.2 SW5.15 U35.22(OEn) U46.22(OEn) U57.18(P15)
MDIO_MDCLK: R1086.2 ; also on sheet 47 48 65
MDIO_MDIO: R1085.2 ; also on sheet 47 48 65
MMC2_BOOT_OVR: R791.2 U119.18(P15) U140.2(I)
MMC2_BOOT_OVR_OEN: R792.2 U119.17(P14) U140.1(OE)
MMC2_SELn: R459.2 R794.2 SW5.18 U57.15(P12) ; also on sheet 13 70
MMC3_SEL: U119.16(P13) ; also on sheet 51
MMC4_CLK: R587.2 U104.4(B) ; also on sheet 62
MMC4_CMD: R520.2 U100.16(B4) ; also on sheet 62
MMC4_DAT0: R521.2 U100.15(B5) ; also on sheet 62
MMC4_DAT1: R522.2 U100.14(B6) ; also on sheet 62
MMC4_DAT2: R523.2 U100.13(B7) ; also on sheet 62
MMC4_DAT3: R524.2 U100.12(B8) ; also on sheet 62
MMC_PWR_ON: U57.9(P5) ; also on sheet 30
NAND_SELn: R239.2 SW5.20 U57.13(P10) ; also on sheet 27
NOR_ALT_ADDRn: R215.2 SW5.14 U57.10(P6) ; also on sheet 24
NOR_BOOTn_OVR: R789.2 U119.20(P17) U139.2(I)
NOR_BOOTn_OVR_OEN: R790.2 U119.19(P16) U139.1(OE)
NOR_SELn: R234.2 R793.2 SW5.19 U57.14(P11) ; also on sheet 28
PCF8575_INT: R638.1 R647.2 R785.1 R786.1 ; also on sheet 25 50
PCI_CONN_REFN: C262.1 U9.5(OUT0N)
PCI_CONN_REFP: C259.1 U9.6(OUT0P)
PCI_PORz: R76.1 U11.4(O) ; also on sheet 11
PCI_RESET_SEL: R201.2 RU13.1(OE) SW5.13 U11.1(OE)
PCI_SW_RESETn: R434.2 U17.1(B) U58.17(P14)
PCM_CLK: P9.52 U41.13(1B1)
PCM_DIN: P9.56 U41.11(2B1)
PCM_DOUT: P9.58 U35.15(B7)
PCM_FSYNC: P9.54 U41.12(1B2)
PHY_1V1: C1068.1 C1069.1 R1102.1 U1032.9(VOUT1) U1032.10(VOUT2) ; also on sheet 47 48
PHY_2V5: C238.1 C239.1 R346.1 U80.9(VOUT1) U80.10(VOUT2) ; also on sheet 47 48
PM_OEn: U119.4(P0) ; also on sheet 59
PM_SEL: U119.7(P3) ; also on sheet 59
PMIC_OFF: U110.2(I) ; also on sheet 11 56
QSH_REF_CLK: P15.10 R1074.2 R1075.2
QSH_RESETn: P15.14 R1072.2 R1073.2
QSH_SCL: P15.2 R1068.2 R1069.2
QSH_SDA: P15.4 R1070.2 R1071.2
QSH_SPI[1]_CS[0]n: P15.22 R1062.2 R1063.2
QSH_SPI[1]_MOSI: P15.18 R1064.2 R1065.2
QSH_SPI[1]_SCLK: P15.20 R1066.2 R1067.2
QSPI_SELn: R470.2 SW5.17 U57.16(P13) ; also on sheet 70
REFCLKn: C262.2 P7.A14(REFCLK-) R79.1
REFCLKp: C259.2 P7.A13(REFCLK+) R79.2
RSTOUTn: R1073.1 U9.12(RSTn) U144.1(OE) U1030.9(A7) ; also on sheet 3 11 26 28 29 34 56 59
SEL_CSI2n: R1055.2 RU114.1(S) U119.13(P10)
SEL_ENET_MUX_S0: U57.8(P4) ; also on sheet 65
SEL_GPMC_AD_VID_S0: U57.4(P0) ; also on sheet 63 68
SEL_GPMC_AD_VID_S2: U57.11(P7) ; also on sheet 63
SEL_I2C3_CAN2: U57.7(P3) ; also on sheet 67
SEL_UART3_SPI2: U57.19(P16) ; also on sheet 67
SERDES_IN_REFN: U9.2(OUT1N) ; also on sheet 71
SERDES_IN_REFP: U9.3(OUT1P) ; also on sheet 71
SLEEP_CLK: P9.1 R222.2
TMP102_ALERT: U58.20(P17) ; also on sheet 69
TS_LCD_GPIO1: J15.9 U58.4(P0)
TS_LCD_GPIO2: J15.10 U58.5(P1)
TS_LCD_GPIO3: J15.11 U58.6(P2)
TS_LCD_GPIO4: J15.12 U58.7(P3)
TS_LCD_IRQ: J15.15 R636.1 TP52.1(TP) ; also on sheet 62
UART3_CTS: U35.8(A6) ; also on sheet 67
UART3_RTS: U46.9(A7) ; also on sheet 67
UART3_RXD: U35.7(A5) ; also on sheet 67
UART3_TXD: U46.10(A8) ; also on sheet 67
UART_SEL1_3: R383.2 SW5.16 U57.17(P14) ; also on sheet 33
USB1_ID: U57.5(P1) ; also on sheet 32
USB1_VBUS_OCN: U58.15(P12) ; also on sheet 31
USB2_ID: U57.6(P2) ; also on sheet 32
USB2_VBUS_OCN: U58.16(P13) ; also on sheet 31
USER_LED1: DS1.1(cathode) U58.8(P4)
USER_LED2: DS2.1(cathode) U58.9(P5)
USER_LED3: DS3.1(cathode) U58.10(P6)
USER_LED4: DS4.1(cathode) U58.11(P7)
VOUT3B_CLK: U3.10(PCLK) ; also on sheet 68
VOUT3B_D0: U3.43(B0/O4) ; also on sheet 63
VOUT3B_D1: U3.44(B1/I2S_DB/O5) ; also on sheet 63
VOUT3B_D2: U3.45(B2) ; also on sheet 63
VOUT3B_D3: U3.46(B3) ; also on sheet 63
VOUT3B_D4: U3.47(B4) ; also on sheet 63
VOUT3B_D5: U3.48(B5) ; also on sheet 63
VOUT3B_D6: U3.1(B6) ; also on sheet 63
VOUT3B_D7: U3.2(B7) ; also on sheet 63
VOUT3B_D8: U3.35(G0/IO2) ; also on sheet 63
VOUT3B_D9: U3.36(G1/IO3) ; also on sheet 63
VOUT3B_D10: U3.37(G2) ; also on sheet 63
VOUT3B_D11: U3.38(G3) ; also on sheet 63
VOUT3B_D12: U3.39(G4) ; also on sheet 63
VOUT3B_D13: U3.40(G5) ; also on sheet 63
VOUT3B_D14: U3.41(G6) ; also on sheet 63
VOUT3B_D15: U3.42(G7) ; also on sheet 63
VOUT3B_D16: U3.25(R0/IO0) ; also on sheet 63
VOUT3B_D17: U3.26(R1/IO1) ; also on sheet 63
VOUT3B_D18: U3.27(R2) ; also on sheet 63
VOUT3B_D19: U3.28(R3) ; also on sheet 63
VOUT3B_D20: U3.29(R4) ; also on sheet 63
VOUT3B_D21: U3.32(R5) ; also on sheet 63
VOUT3B_D22: U3.33(R6) ; also on sheet 63
VOUT3B_D23: U3.34(R7) ; also on sheet 63
VOUT3B_DE: U3.5(DE) ; also on sheet 68
VOUT3B_HSYNC: U3.3(HS) ; also on sheet 68
VOUT3B_INTB: R22.2 U3.31(INTB) ; also on sheet 68
VOUT3B_VSYNC: U3.4(VS) ; also on sheet 68
VSYS_3V3: C18.1 C1067.1 P7.A9(+3.3V.2) P7.A10(+3.3V.3) P7.B8(+3.3V.1) U80.1(IN1) U80.2(IN2) U1032.1(IN1) U1032.2(IN2) ; also on sheet 11 23 52 54 55 56 57 58
VSYS_5V0: C705.1 C1071.1 U80.4(BIAS) U1032.4(BIAS) ; also on sheet 54 56 58
WL_EN: P9.4 U46.19(B3)
WLAN_IRQ: P9.34 U35.21(B1)
N17473174: C215.2 P1.2
N17473178: C216.1 P1.4
N18472008: R752.1 R754.2 U119.21(A0)
N18472026: R749.1 R753.2 U119.3(A2)
N18472030: R750.2 R751.1 U119.2(A1)
N19012744: R615.1 U54.8(STB) U110.4(O)
N19184134: P9.12 TP49.1(TP)
N19184365: P9.14 TP46.1(TP)
N19184698: P9.16 TP44.1(TP)
N19185088: P9.73 TP23.1(TP)
N19240062: R85.2 SW2.11(B6)
N19240090: R86.2 SW2.10(B7)
N19240118: R87.2 SW2.9(B8)
N19692324: R80.2 SW2.16(B1)
N19692326: R81.2 SW2.15(B2)
N19692328: R82.2 SW2.14(B3)
N19692409: R83.2 SW2.13(B4)
N19692411: R84.2 SW2.12(B5)
N21014314: C36.1 U9.17(REG_CAP2)
N21014318: C39.1 U9.19(REG_CAP1)
N21014360: C42.2 U9.21(XIN) Y2.1(Y1)
N21014402: R62.1 R63.2 U9.11(OS0)
N21014404: R64.2 R65.1 U9.10(OS1)
N21014459: TP6.1 U9.23(OSCOUT)
N21014498: R70.2 R71.1 U9.7(0E)
N21014569: C42.1 R75.1 Y2.3(C1)
N21264274: R786.2 U57.1(~{INT})
N21264312: R785.2 U119.1(~{INT})
N21725902: C532.1 U56.7(SS)
N21725906: C515.2 R241.1 R244.2 U56.8(FB)
N21763494: R638.2 U58.1(~{INT})
N22076457: C3.1 P4.18(+5V) U1.12(5V_OUT)
N22078761: R178.1 R528.2 U41.2(1DIR)
N22078791: R157.1 R519.2 U41.3(2DIR)
N22078885: R715.1 U35.14(B8) U35.20(B2)
N22078887: R515.1 U41.14(2~{OE}) U41.15(1~{OE})
N22080024: R714.2 U46.3(A1) U46.7(A5) U46.8(A6)
N22085834: R794.1 U140.4(O)
N22085848: R793.1 U139.4(O)
N22206221: P9.76 TP22.1(TP)
N22223983: P9.11 TP48.1(TP)
N22225609: P9.13 TP47.1(TP)
N22227190: P9.15 TP45.1(TP)
N22323953: R222.1 Y9.3(OUT)
N22623561: P7.B17(~{PRSNT2}) R439.2
N23173932: R660.1 R665.2 U58.21(A0)
N23173950: R655.1 R662.2 U58.3(A2)
N23173954: R639.2 R648.1 U58.2(A1)
N23236371: P7.A6(TDI) R416.2
N23236373: P7.A8(TMS) R415.2
N23236393: R420.1 U12.1(~{RESE}T) U16.1(~{RESE}T) U17.2(A)
N23236395: R98.2 R99.2 U12.5(SENSE1)
N23236416: C279.1 U12.4(CT)
N23236432: P7.A5(TCK) R421.1
N23236438: P7.B9(TRSTn) R448.1
N23236460: P7.A11(PERSTn) R413.1 RU13.4(O) U11.2(I)
N23236584: R104.2 R106.2 U16.5(SENSE1)
N23236602: C292.1 U16.4(CT)
N23236629: P7.A1(~{PRSNT1}) R439.1
N23237357: RU13.2(I) U17.4(Y)
N23318790: R765.2 U15.4(Y)
N24177826: R1060.2 U1029.7(VREF2) U1029.8(EN)
N24178242: C1062.1 L1006.1 U4.4(VCC)
N24431145: J1002.26 R1084.2
N24500715: J5.33 R828.1 U144.4(O)
N25225056: R603.2 U50.7(VREF2) U50.8(EN)
N25448312: C1066.1 U1032.7(SS)
N25448316: C1069.2 R1102.2 R1103.1 U1032.8(FB)
N25448328: R833.1 RJ2.2 U1032.5(EN)
N25472068: C19.1 U80.7(SS)
N25472072: R832.1 RJ1.2 U80.5(EN)
N25472435: C239.2 R24.1 R346.2 U80.8(FB)
N26356798: DS4.2(ANODE) R682.2
N26356799: DS3.2(ANODE) R677.2
N26356800: DS2.2(ANODE) R676.2
N26356801: DS1.2(ANODE) R674.2
N26498318: JP1.1 R238.1 U54.7(CANH)
N26498320: JP1.3 R255.2 U54.6(CANL)
N27808158: C525.1 R238.2 R255.1
N30079472: R88.2 SW3.16(B1)
N30079474: R89.2 SW3.15(B2)
N30136123: R90.2 SW3.14(B3)
N30136125: R91.2 SW3.13(B4)
N30139026: R92.2 SW3.12(B5)
N30139028: R93.2 SW3.11(B6)
N30141933: R94.2 SW3.10(B7)
N30141935: R95.2 SW3.9(B8)
N32448034: R585.2 SW5.8
N32450953: R594.2 SW5.7
N32453874: R599.2 SW5.6
N32462658: R612.2 SW5.2
N32462660: R619.2 SW5.1
N32462662: R610.2 SW5.3
N32468327: R604.2 SW5.4
N32471262: R601.2 SW5.5
N32733566: R332.2 R333.1 U3.24(MODE_SEL)
N32742919: C235.1 C236.1 L3.2 U3.30(VDDIO)
N32792459: C229.1 C231.1 L2.1 U3.22(VDD33)
N32801911: C8.1 U3.14(CAPP12)
N32804282: C13.1 C234.1 U3.7(CAPL12)
N32806655: C7.1 U3.17(CAPHS12)
N32835273: C232.1 U3.23(CMF)
N32856854: C5.1 U3.20(DOUT+)
N32861613: C6.1 U3.19(DOUT-)
N32916975: R20.2 R338.1 U3.6(IDX)
N33052757: J5.27 R60.2
N33052765: J5.23 RN8.3(R3A)
N33052767: J5.24 RN8.4(R4A)
N33052820: J5.22 RN8.2(R2A)
N33052822: J5.21 RN8.1(R1A)
N33052958: J5.7 TP5.1
N33053022: J5.19 RN9.3(R3A)
N33053024: J5.20 RN9.4(R4A)
N33053026: J5.18 RN9.2(R2A)
N33053028: J5.17 RN9.1(R1A)
N33053058: J5.15 RN10.3(R3A)
N33053060: J5.16 RN10.4(R4A)
N33053062: J5.14 RN10.2(R2A)
N33053064: J5.13 RN10.1(R1A)
N33053104: J5.9 R58.2
N33053172: J5.11 R59.2
N33053182: J5.12 R353.2
N33053241: J5.28 R356.2
N33151523: R10.1 U3.11(I2S_DA/O6)
N33156530: R9.1 U3.12(I2S_WC/O7)
N33159038: R11.1 U3.13(I2S_CLK/O8)
N33161549: C228.1 R8.2 U3.21(PDB)
N33988069: R661.1 R666.2 U57.21(A0)
N33988087: R656.1 R663.2 U57.3(A2)
N33988091: R640.2 R649.1 U57.2(A1)
N43244613: R579.2 SW5.9
N43259312: R569.2 SW5.10

Not connected (* = marked no-connect by the designer): J5 35*; J1002 27* 28* 35* 36*; MHC1 1(TP); MHC2 1(TP); MHC3 1(TP); MHC4 1(TP); P4 14(NC.14)*; P7 A7(TDO) A19(RSVD.3) A25(PERp2) A26(PERn2) A29(PERp3) A30(PERn3) A32(RSVD.4) B5(SMCLK) B6(SMDAT) B10(3.3VAUX) B11(WAKEn) B12(RSVD.1) B23(PETp2) B24(PETn2) B27(PETp3) B28(PETn3) B30(RSVD.2) B31(~{PRSNT2}.2); P9 10* 17* 21* 23* 25* 27* 29* 35* 36* 38* 39* 40* 41* 43* 44* 45* 46* 49 51 53 55 57* 59* 61* 62* 65* 67* 69* 71* 74* 75* 78* 79* 80* 81* 82* 84* 85* 86* 88* 90* 91* 93* 94* 96* 98* 99* 100*; P15 1 3 6 8 26 28 37 39; RU114 5(2B1)*; U1 14(CLK-) 15(CLK+) 16(D0-) 17(D0+) 19(D1-) 20(D1+) 21(D2-) 22(D2+); U3 16(NC.16); U9 8(NC.8) 13(NC.13) 15(NC.15) 24(NC.24) 25(NC.25) 26(NC.26) 27(NC.27) 28(NC.28) 29(NC.29) 30(NC.30) 31(NC.31) 32(NC.32); U12 3(~{MR})*; U16 3(~{MR})*; U35 4(A2) 6(A4) 10(A8) 18(B4); U41 10(2B2); U46 16(B6) 17(B5) 21(B1); U56 3(PG); U57 20(P17); U58 19(P16); U80 3(PG); U100 1(A1) 3(A2) 4(A3); U110 1(NC1); U119 11(P7); U1030 16(B6)* 17(B5)* 18(B4)*; U1032 3(PG); Y9 1(EN)*

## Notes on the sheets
sheet 35
- DIFFERENTIAL PAIR
  100 OHM DIFFERENTIAL
  IMPEDANCE
  SHORT AND STRAIGHT AS
  POSSIBLE,
  MINIMUM NUMBER OF VIAS
- LVDS OUTPUT
  OSCOUT PIN = OFF
- CE = '1' = ON
- OUTCLOCK = 100mHZ
sheet 36
- Reset Threhold 0.84 Volts
- Reset Threhold 0.84 Volts
- Connector must be less than 2.25 inches
  to board edge from key to board edge
sheet 38
- DIFFERENTIAL PAIR
  100 OHM DIFFERENTIAL
  IMPEDANCE
  SHORT AND STRAIGHT AS
  POSSIBLE,
  MINIMUM NUMBER OF VIAS
- DIFFERENTIAL PAIR
  100 OHM DIFFERENTIAL
  IMPEDANCE
  SHORT AND STRAIGHT AS
  POSSIBLE,
  MINIMUM NUMBER OF VIAS
- ER25
- ER25
- THE HDMI I2C SIGNALS ARE
  CROSSED IN VAYU AND NEED TO BE
  UNCROSSED AT THE BOARD LEVEL.
  THIS UNCROSS IS MOVED TO RU108
  ON SHEET 5, REVE.
- REVE
sheet 39
- VOUT3 INTERFACE
- TRANSMIT USES 1 DATA - 3 DATA +
sheet 40
- THESE TERMINATIONS ON CAMERA MAY NOT BE
  NEEDED. THE CAMERA SCHEMATIC APPEARS TO
  HAVE SOURCE TERMS ON BOARD.
- CLOCK LANE
- OPTIONAL
sheet 41
- HVDA541QDRQ1
sheet 42
- EXP1
- EXP2
- REV C
- REV C
- REV C
- REV C
- EXP3
sheet 43
- MMC2 BOOT PULL UP ON PAGE 23 SET TO LOGIC 0 TO
   ENABLE MMC2 MUX FOR BOOTING SET TO 1 FOR GPMC
  BOOTING
- QSPI BOOT PULL UP ON PAGE 23 SET TO LOGIC 0 TO
   ENABLE QSPI MUX FOR BOOTING SET TO 1 FOR GPMC
  BOOTING
- UART SEL1_3 PULL UP ON PAGE 58 SELECTS UART3
  MUX INPUT TO BE USART PORT AT MINI_USB A(J1)
  DURING BOOTING.
  MCASP1_ENn MUST BE SET TO LOGIC 1 TO DISABLE
  COM8. ALSO OTHER MUX NEEDS TO BE IN DEFAULT
  CONFIGURATION
sheet 44
- DIR=H : A to B
  DIR=L : B to A
- L = B TO A
  H = A TO B
- L = B TO A
  H = A TO B
- L = B TO A
  H = A TO B
sheet 45
- Antenna
- VOUT = 0.8 * ( 1+(RTOP/RBOTTOM) )
- 3.6 = 0.8 * ( 1+(RTOP/RBOTTOM ))
- 4.5 = ( 1+(RTOP/RBOTTOM ))
- 3.5 = ((RTOP/RBOTTOM ))
- 3.5 RBOTTOM = RTOP
sheet 46
- ER23
- ER9
- VOUT = 0.8 * ( 1+(RTOP/RBOTTOM) )
- 2.5 = 0.8 * ( 1+(RTOP/RBOTTOM ))
- 2.5 = 0.8 * ( 1+(RTOP/4.99K ))
- 3.125 =  ( 1+(RTOP/4.99K ))
- 2.125 =  (RTOP/4.99K )
- 10.6K =  RTOP
